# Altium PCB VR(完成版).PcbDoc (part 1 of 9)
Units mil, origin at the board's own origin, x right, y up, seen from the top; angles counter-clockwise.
Board outline 2839.68 x 2020.7 mil, 6 copper layers (TOP, GND02, SIN03, SIN04, PWR05, BOTTOM); 494 components, 404 nets, 7124 pads, 1123 vias.
Unrouted connection lines stored in the file: 10.
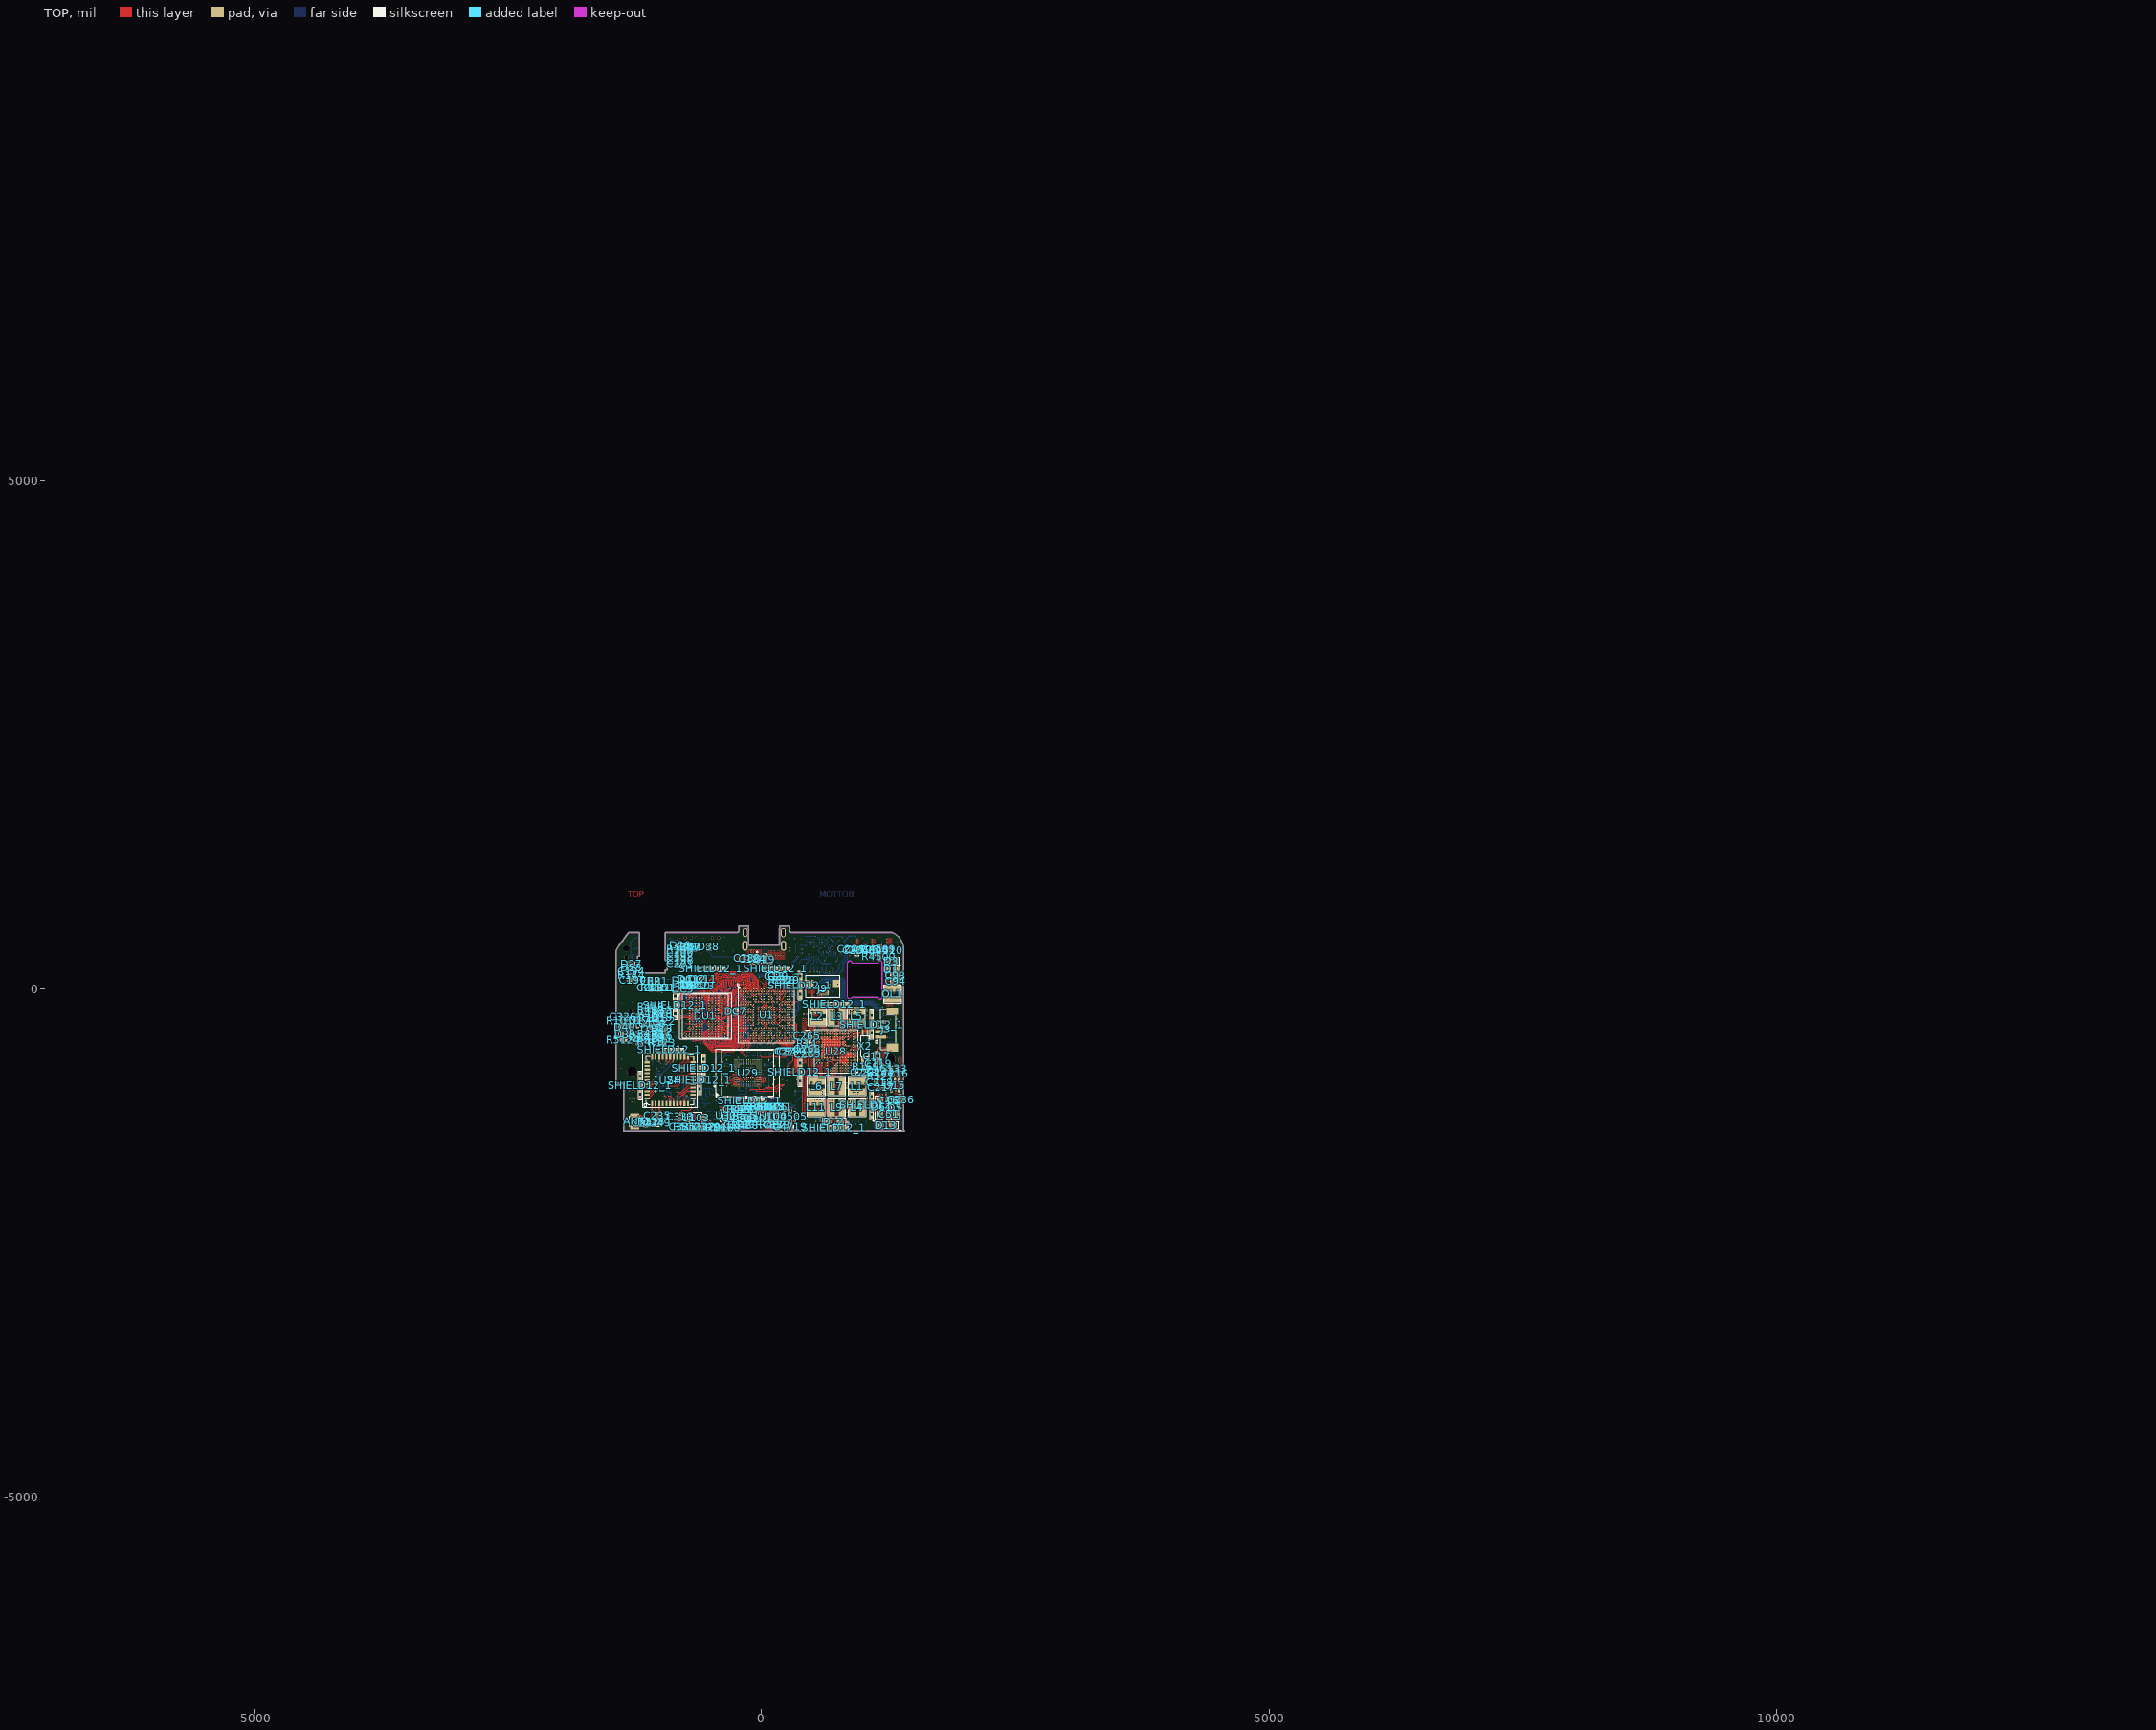
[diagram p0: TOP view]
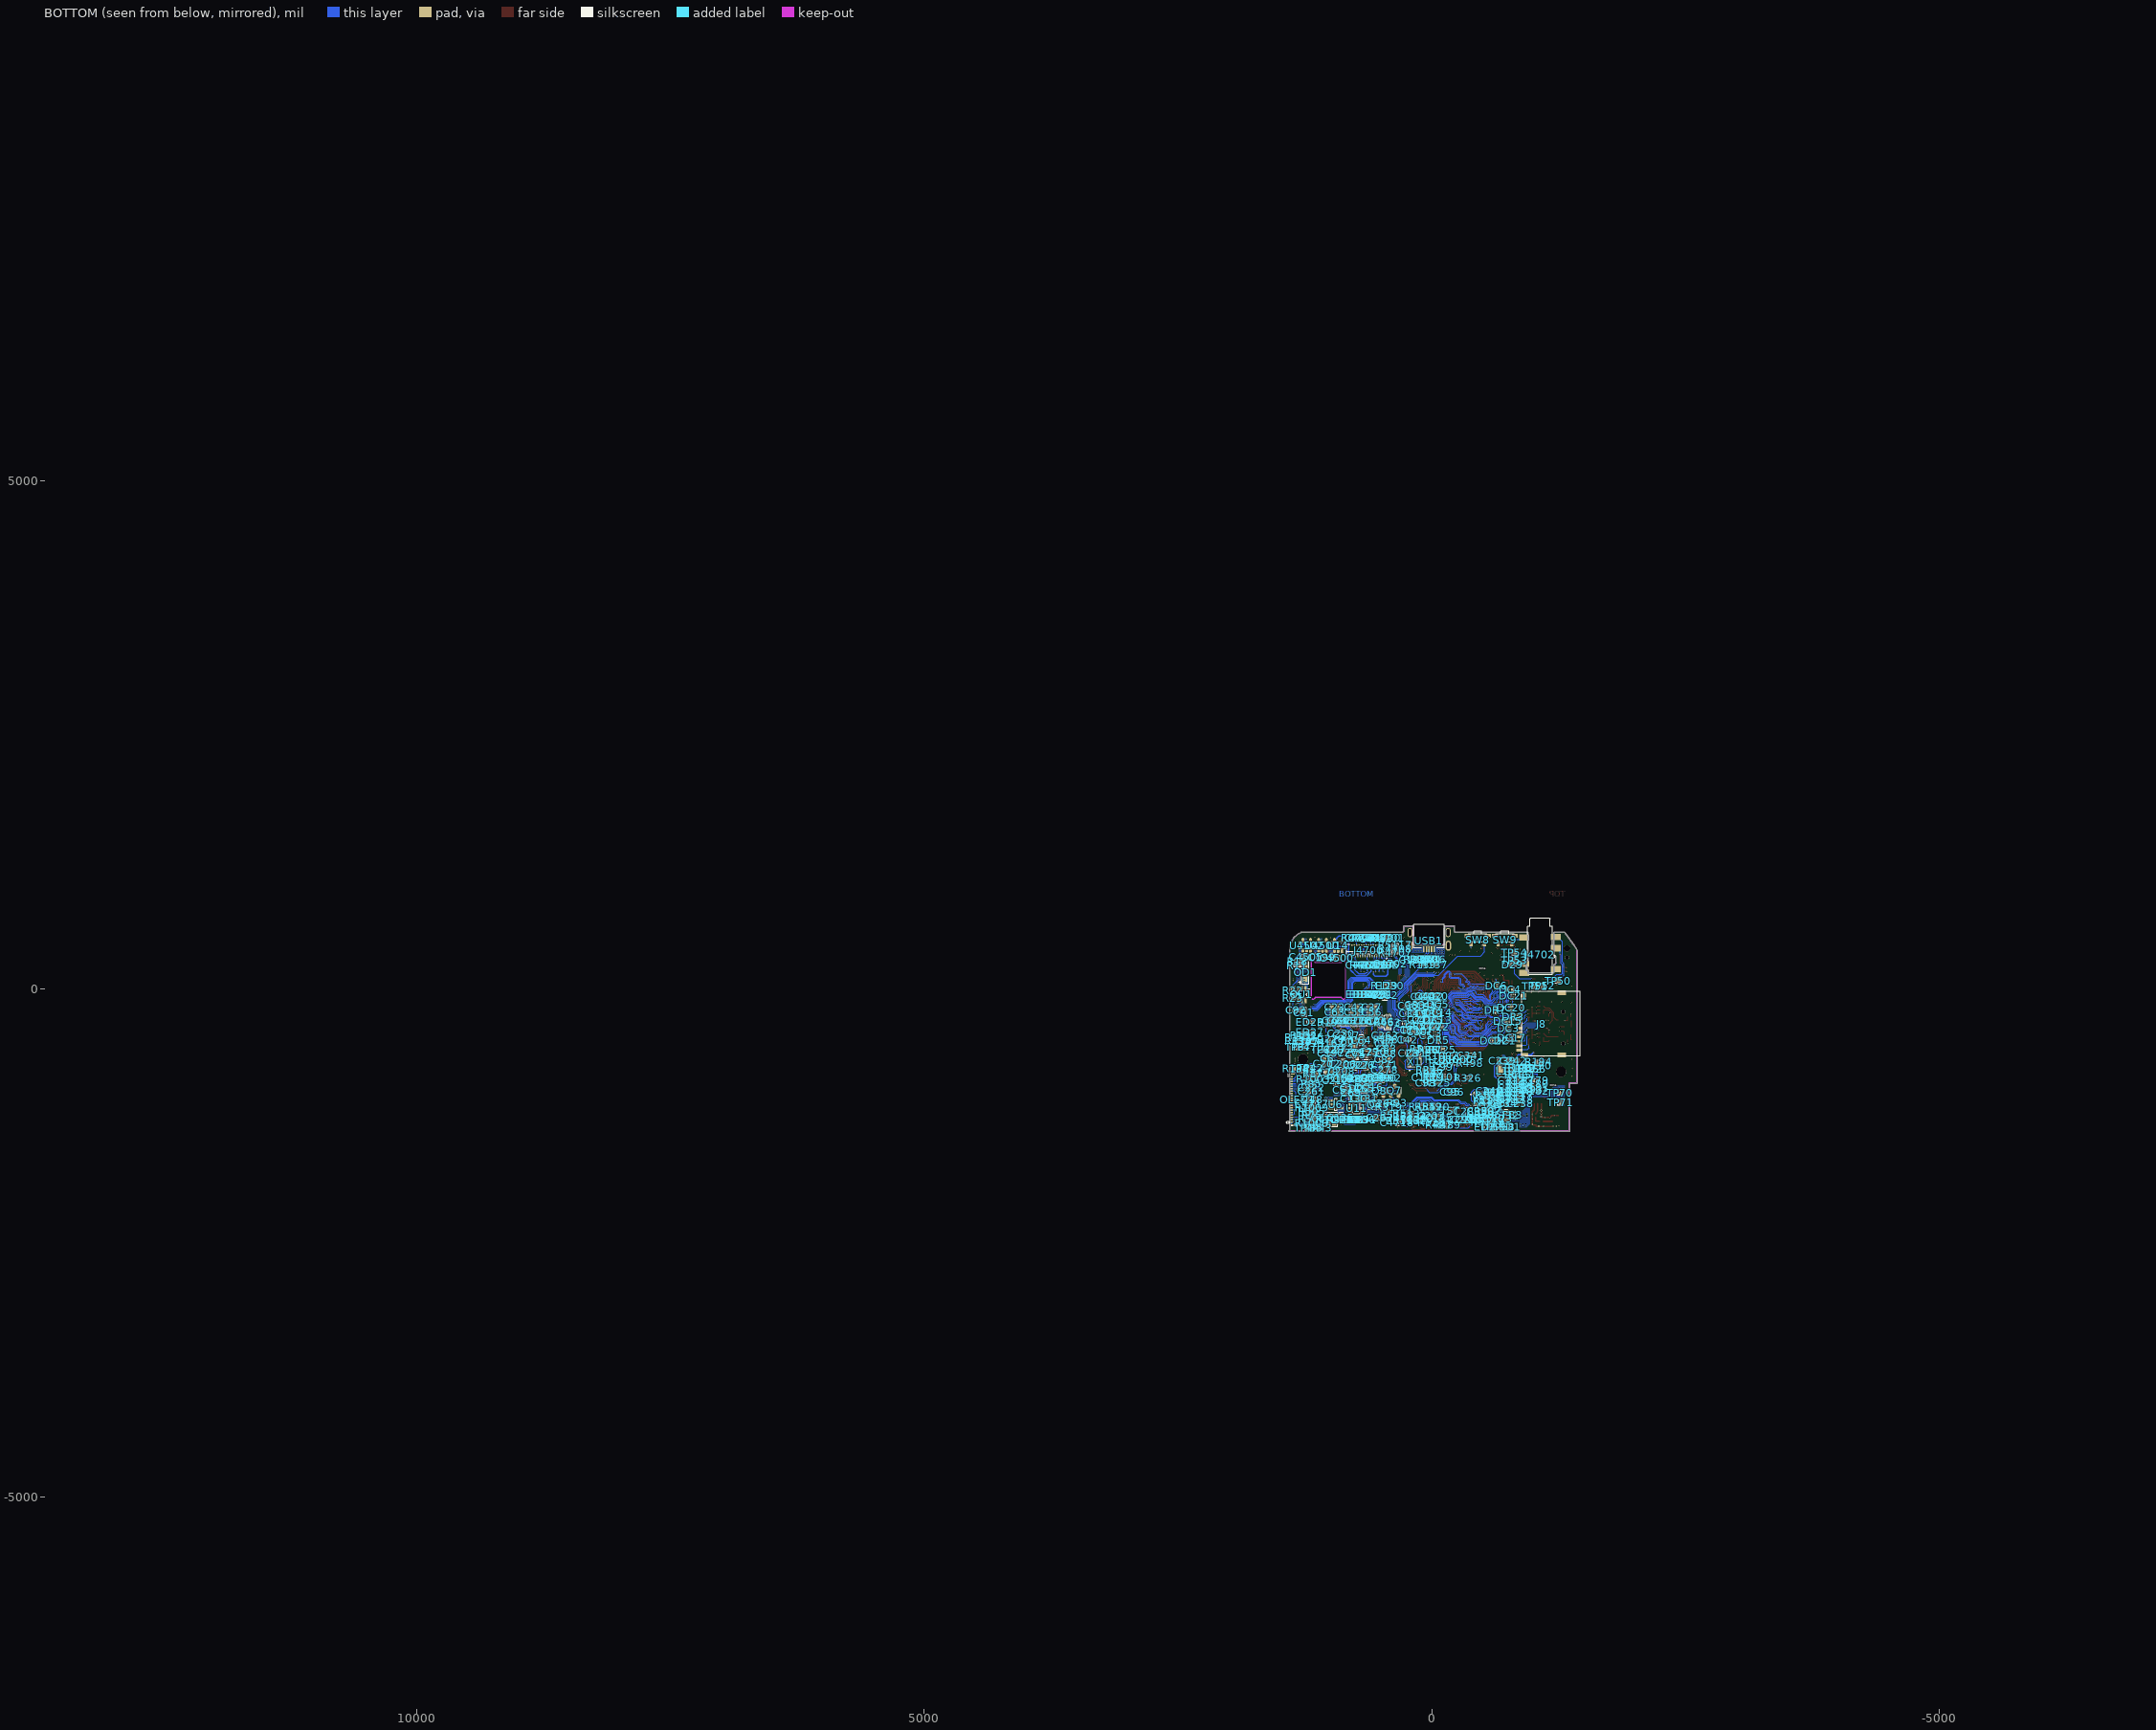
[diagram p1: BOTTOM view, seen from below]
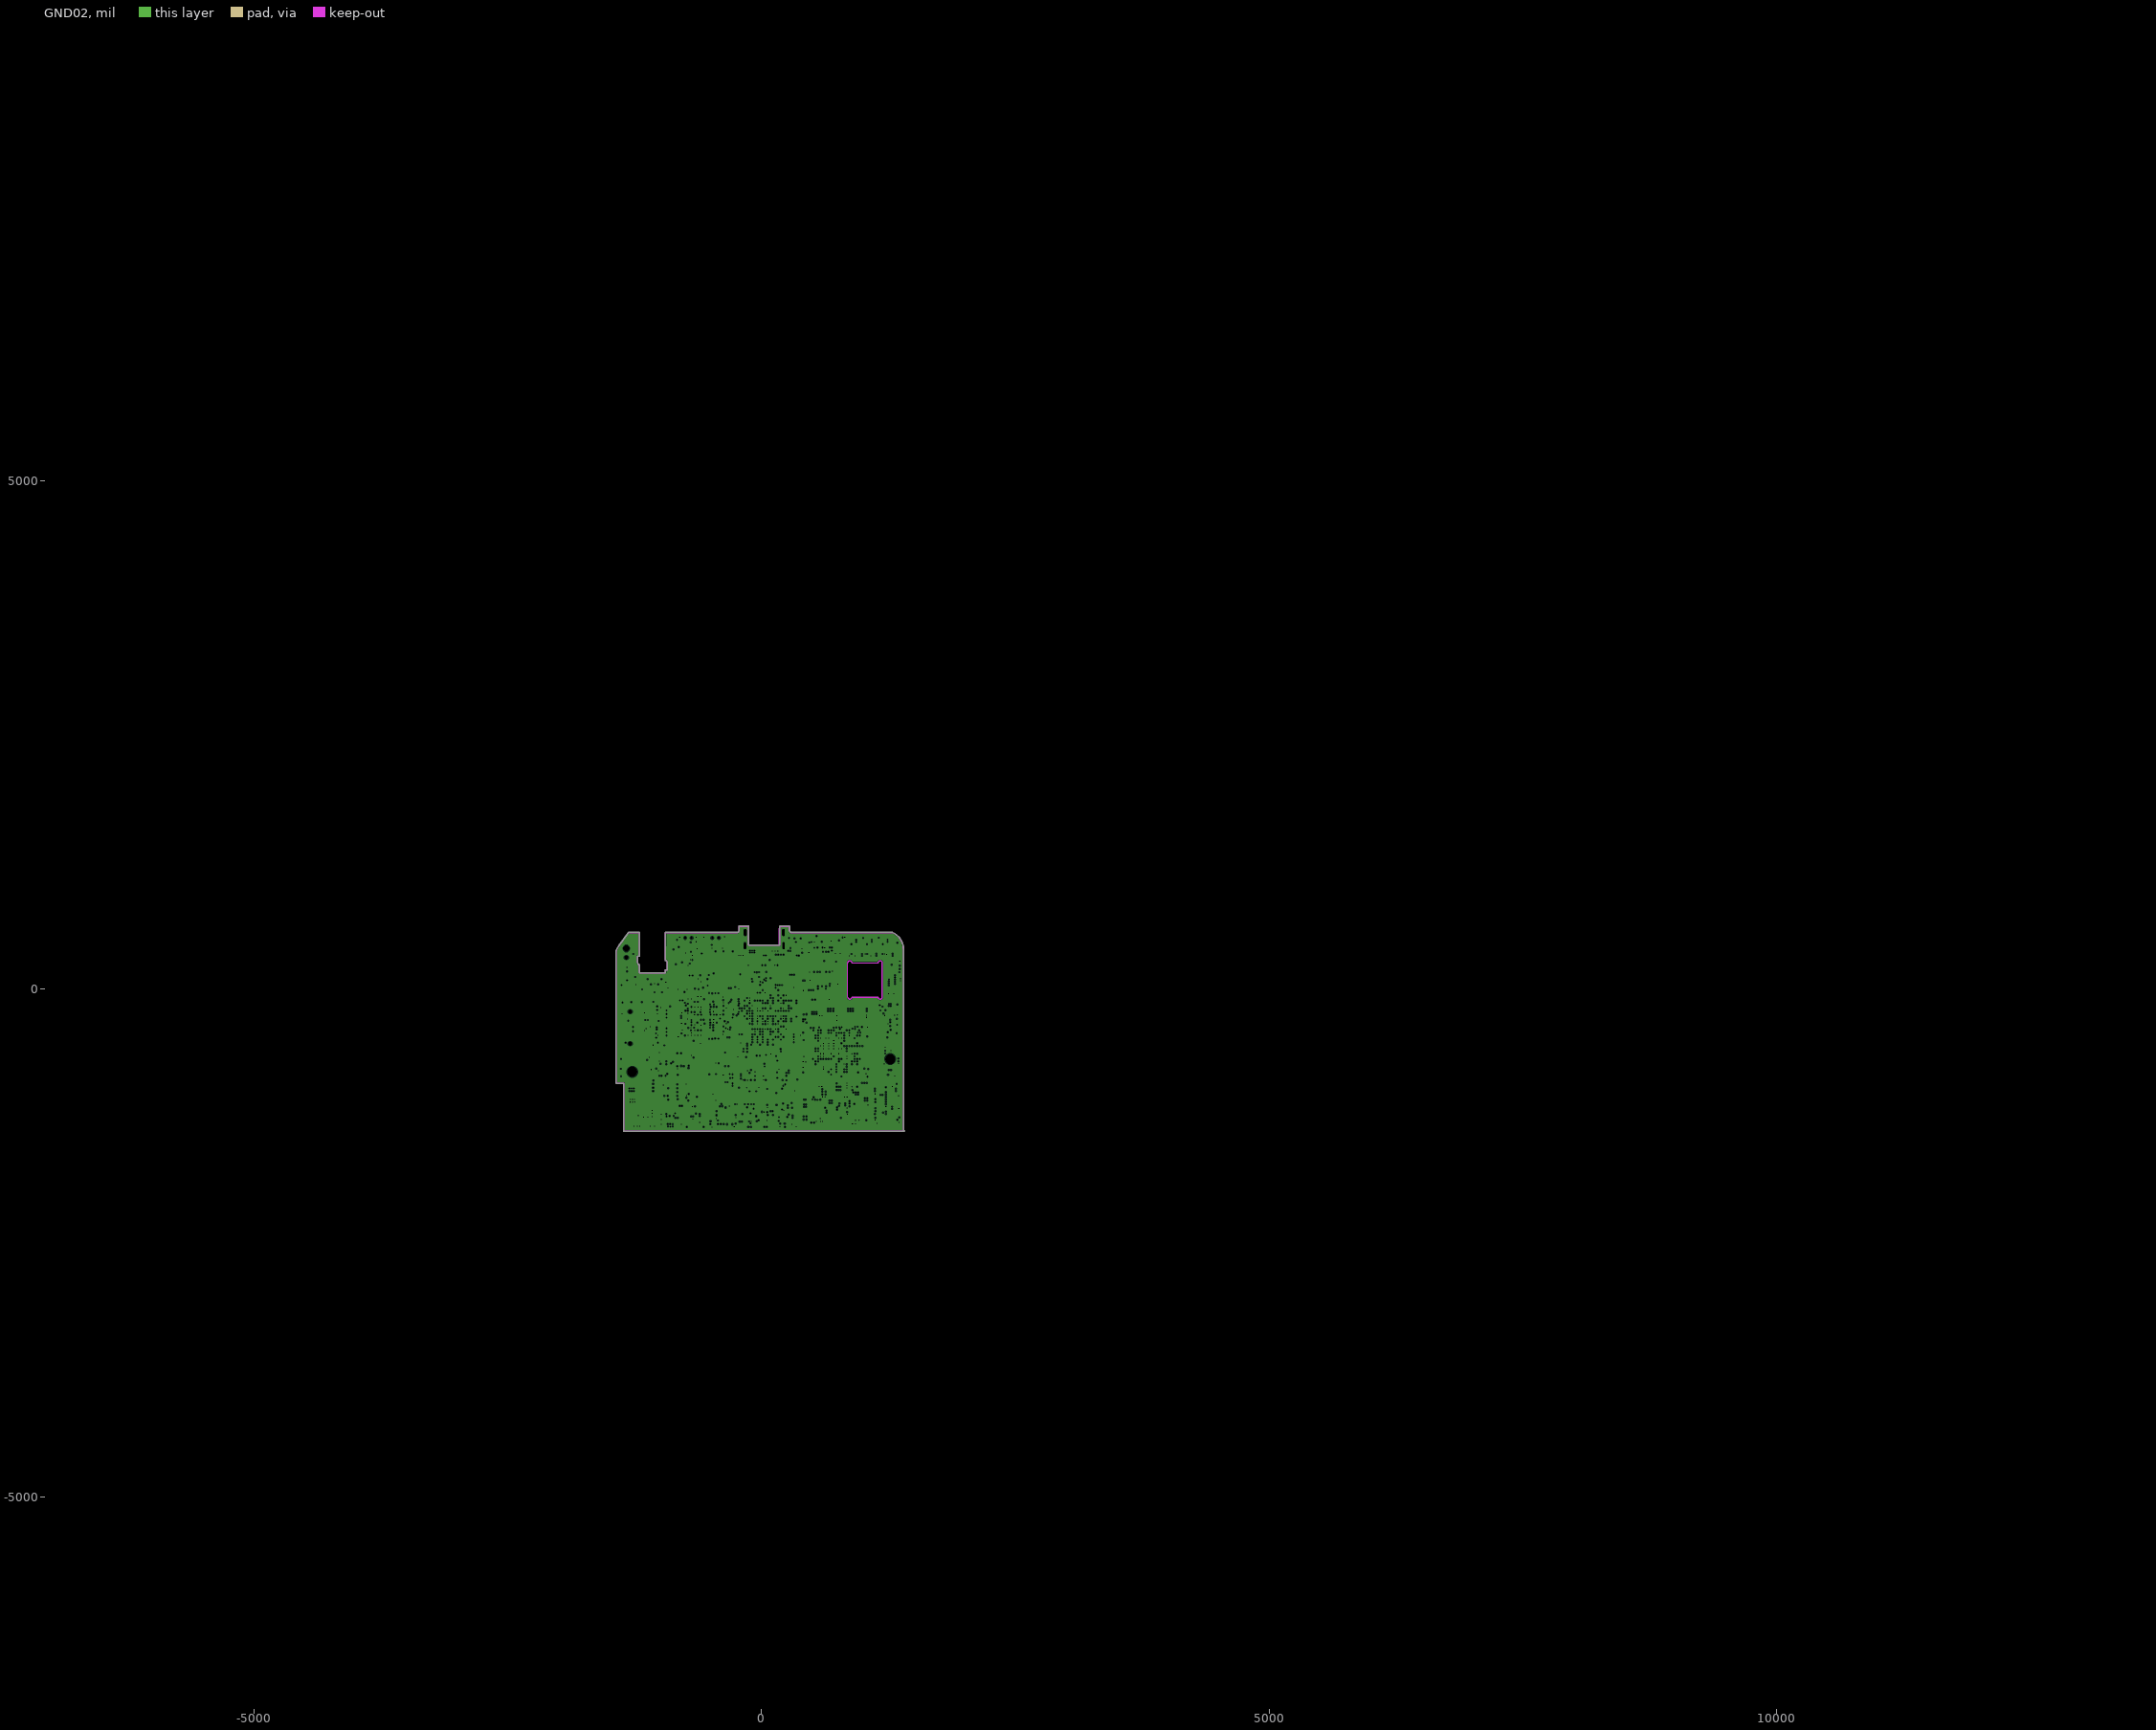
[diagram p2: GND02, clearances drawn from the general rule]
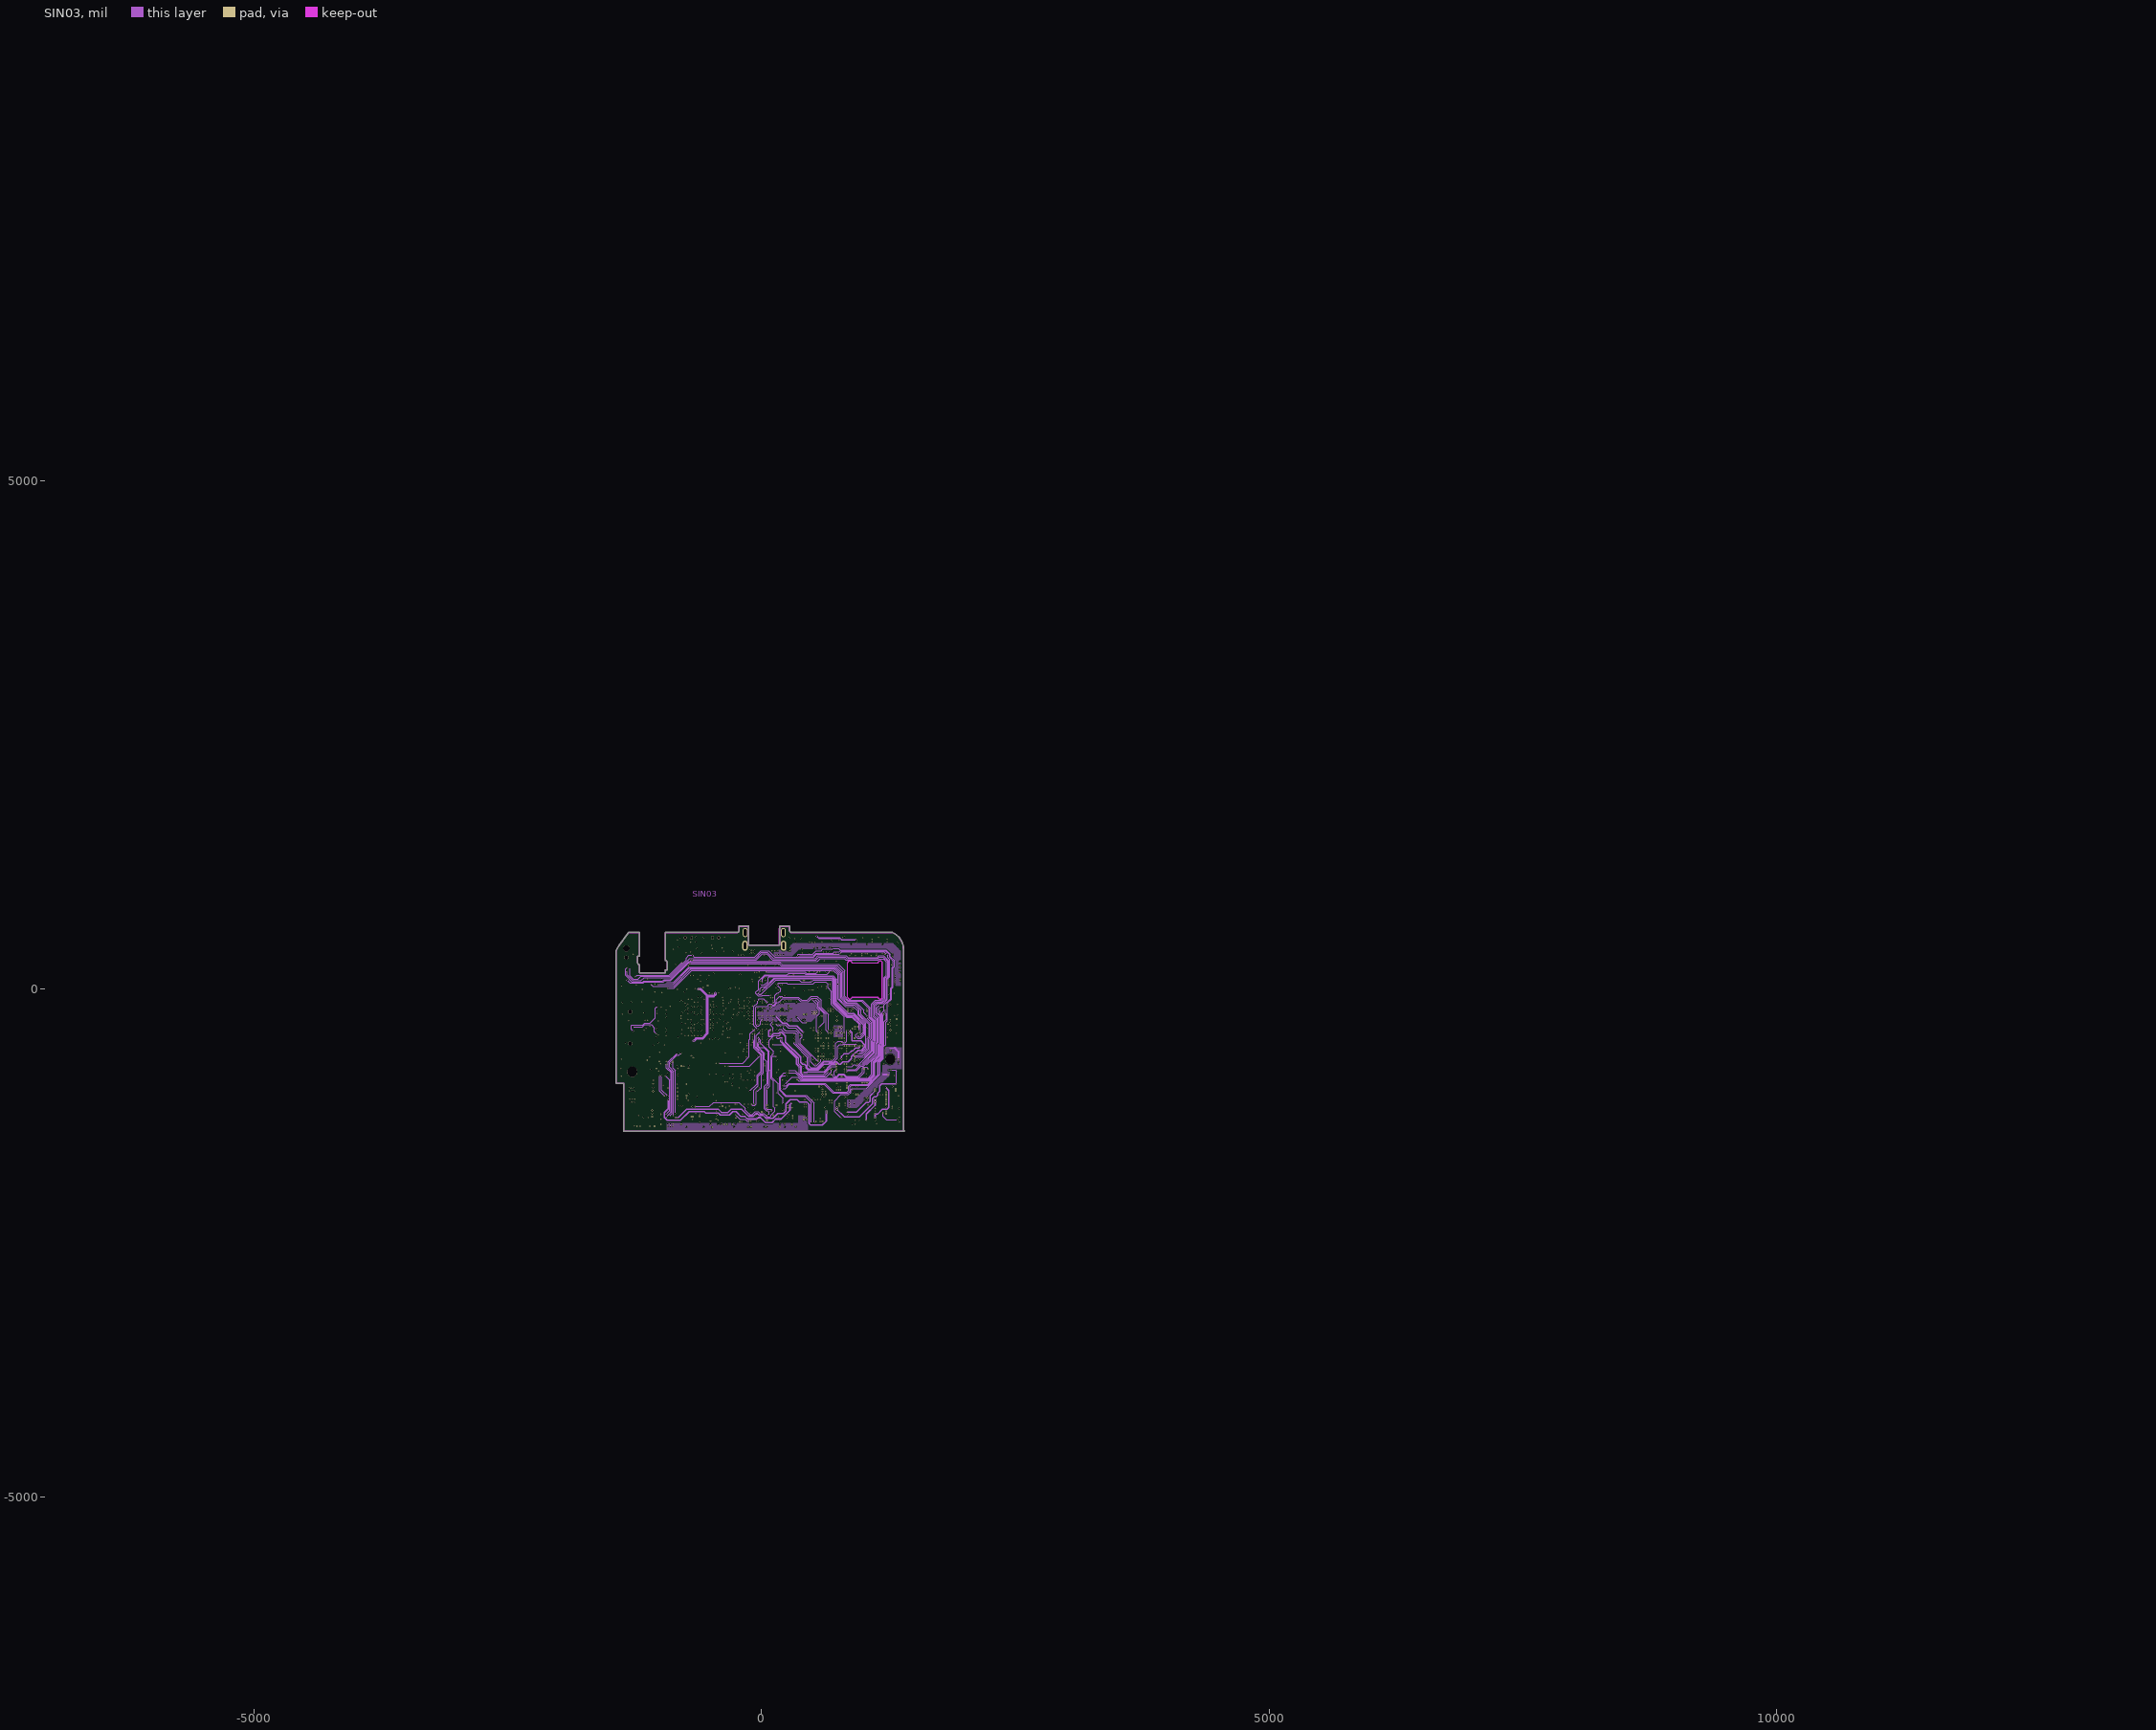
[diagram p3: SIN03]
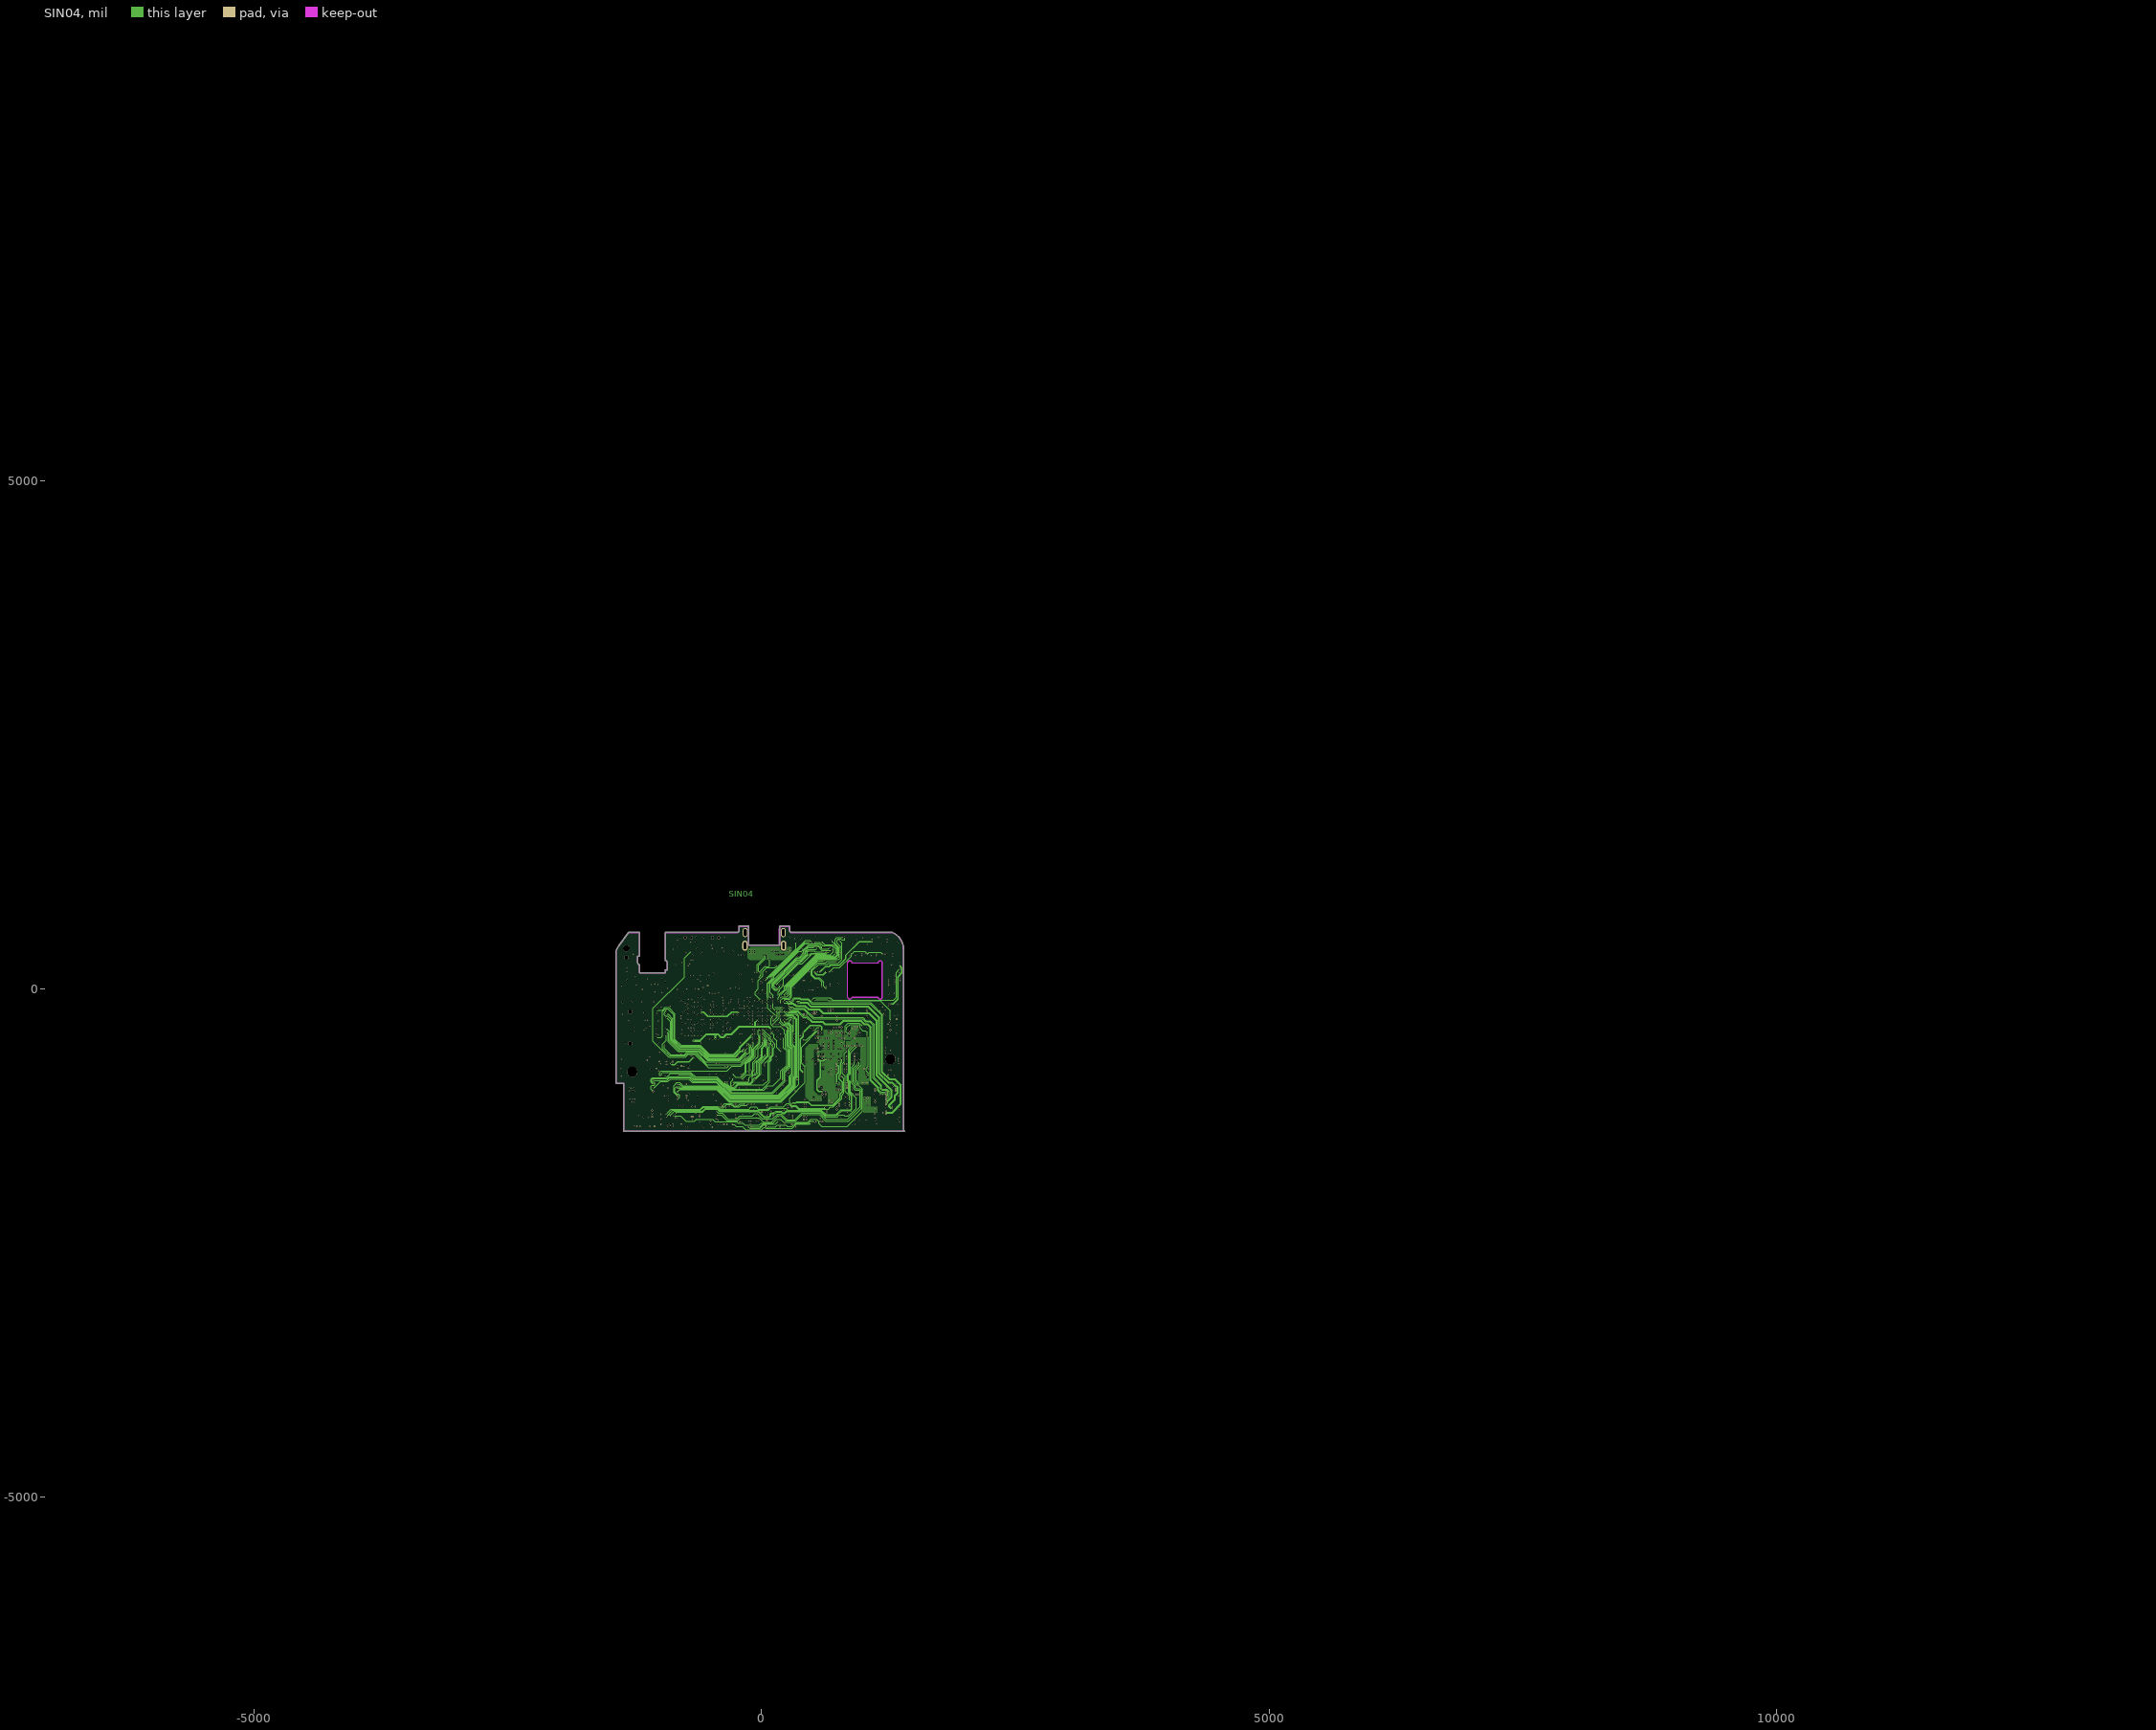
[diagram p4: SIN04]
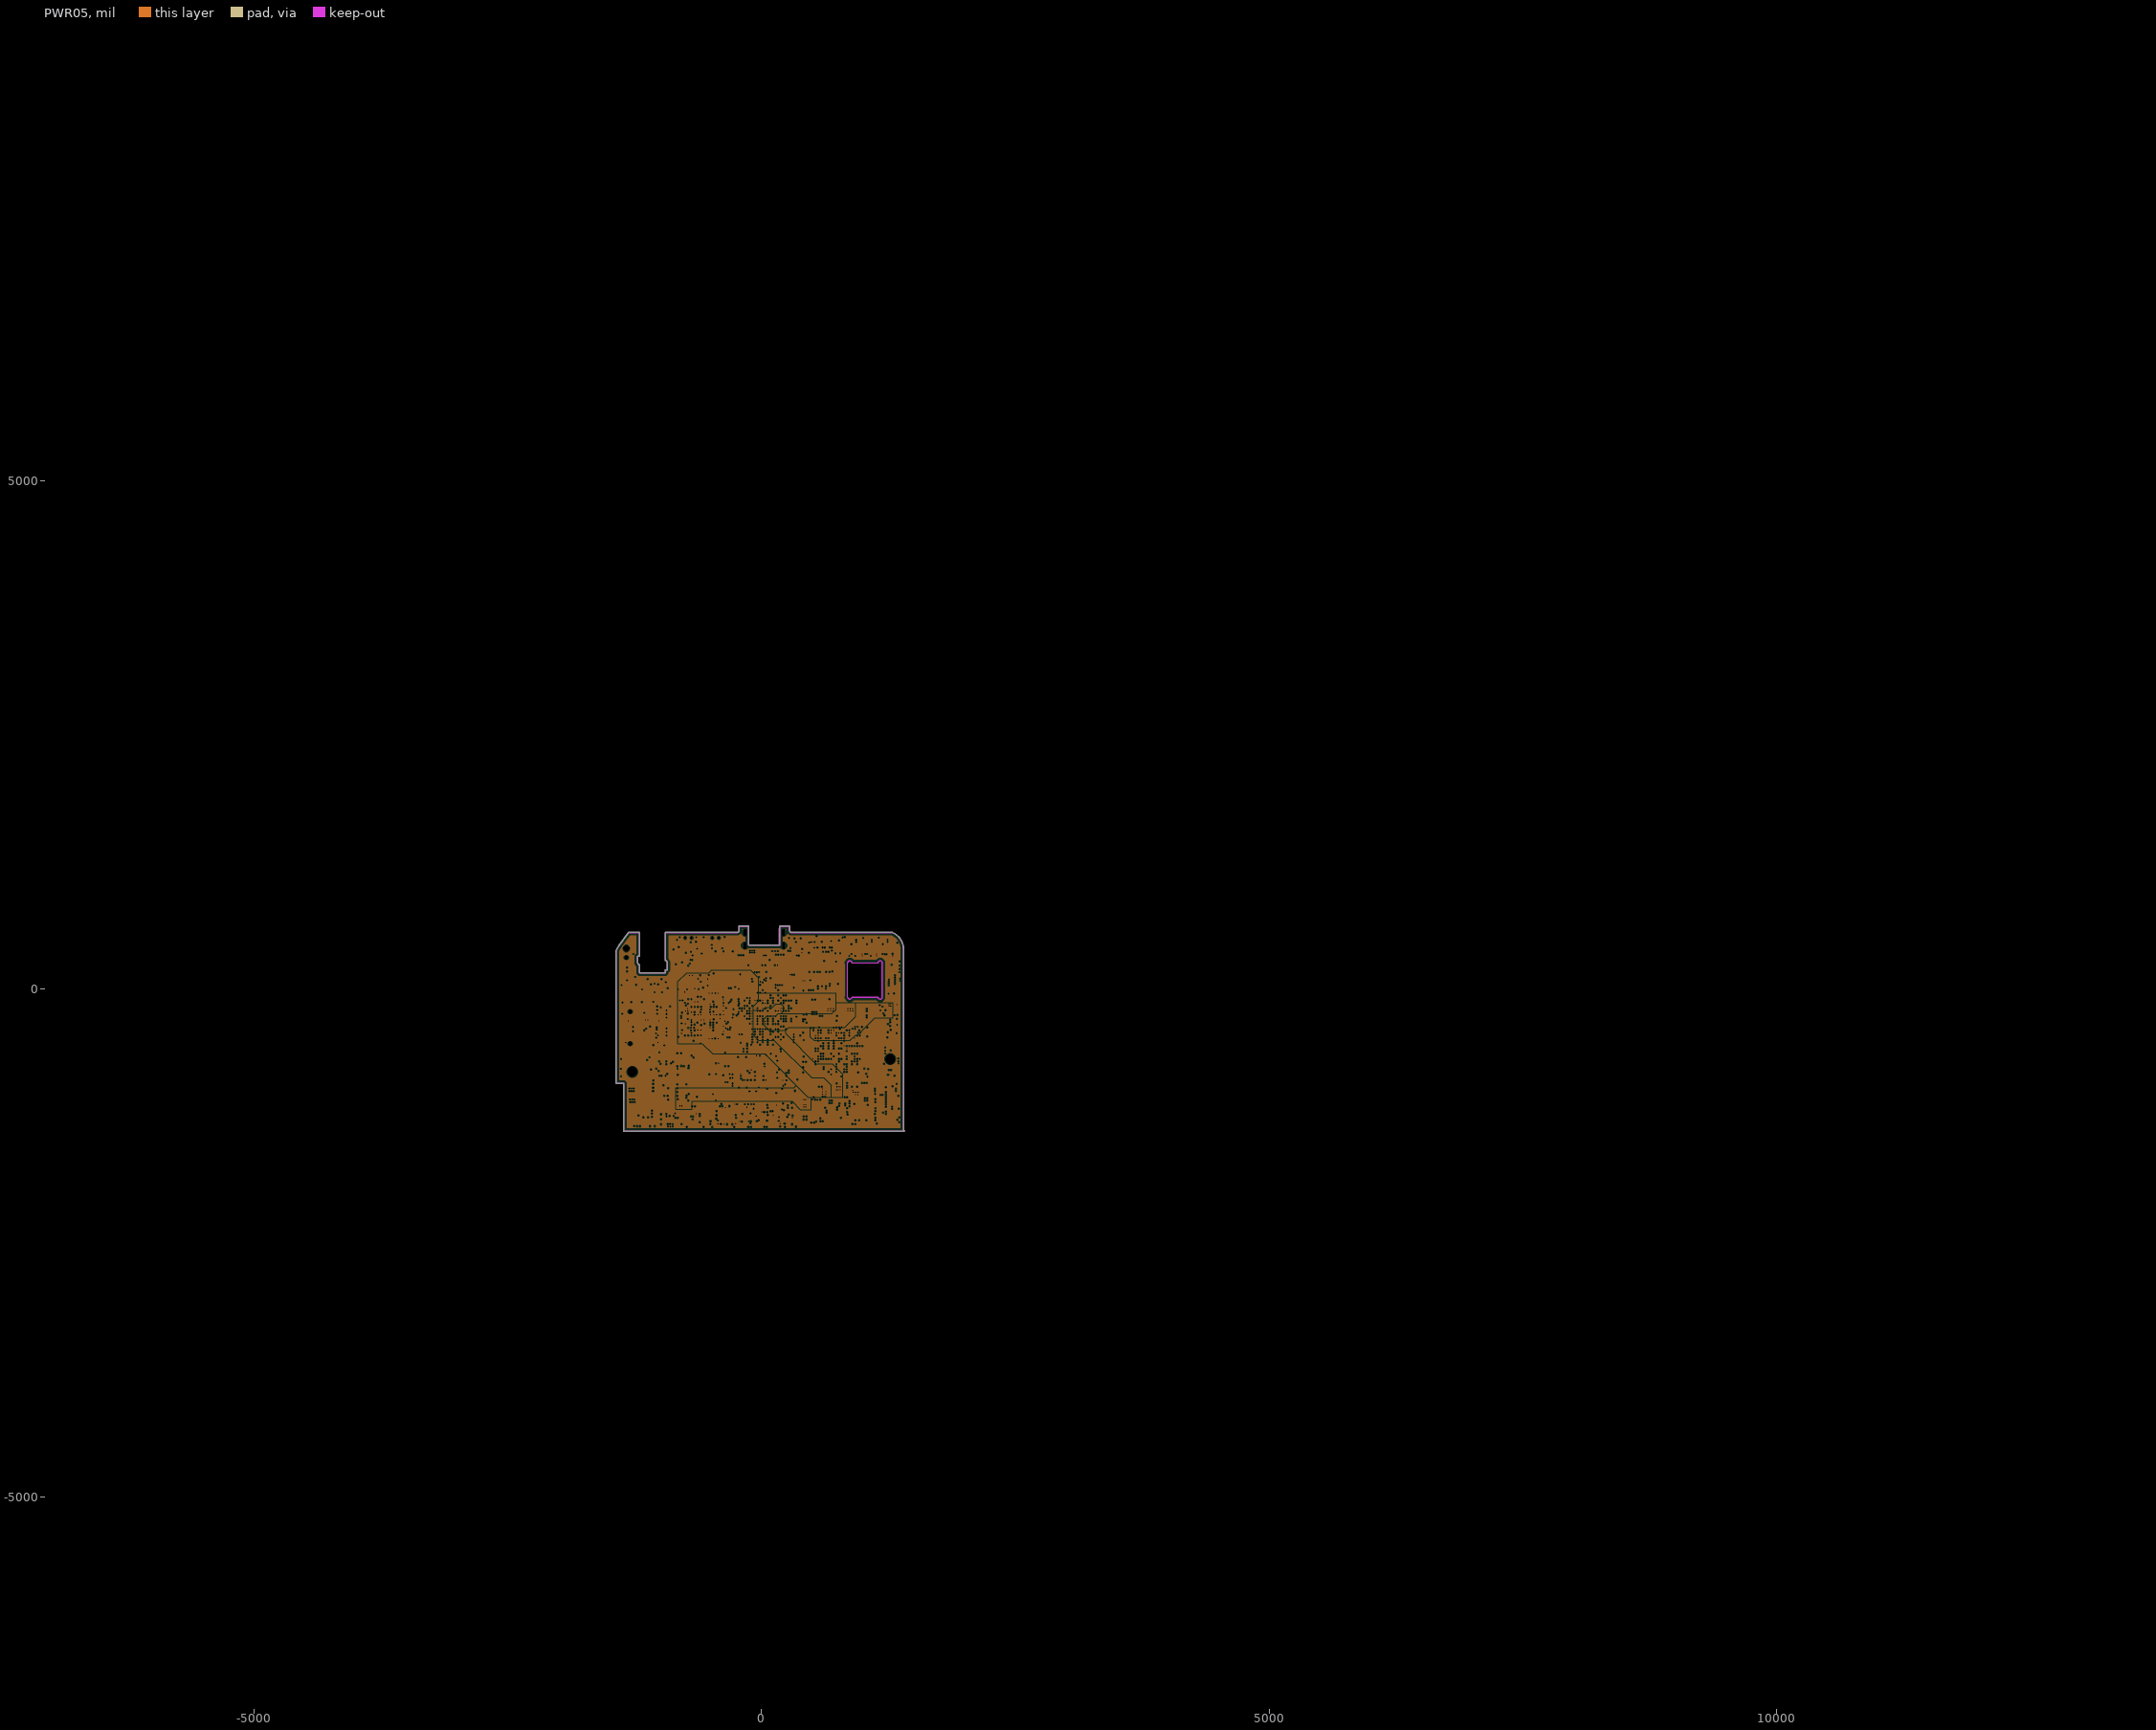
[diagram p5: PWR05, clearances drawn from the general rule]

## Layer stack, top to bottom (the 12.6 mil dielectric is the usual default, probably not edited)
TOP: signal copper 1.4
Dielectric: core 12.6, FR-4, Dk 4.8
GND02: plane copper 1.4, net GND
Dielectric: prepreg 12.6, FR-4, Dk 4.8
SIN03: signal copper 1.4
Dielectric: core 12.6, FR-4, Dk 4.8
SIN04: signal copper 1.4
Dielectric: prepreg 12.6, FR-4, Dk 4.8
PWR05: plane copper 1.4, net DCDC1
Dielectric: core 12.6, FR-4, Dk 4.8
BOTTOM: signal copper 1.4

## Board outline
-1428.06,-929.41 -1355.77,-929.41 -1355.77,-1399.33 ccw(c-1353.25,-1399.33) -1353.25,-1401.85 1406.59,-1401.85 ccw(c1406.59,-1399.33) 1409.11,-1399.33 ccw(c1406.59,-1399.33) 1406.59,-1396.82 1396.58,-1396.82 ccw(c1359.35,-1261.54) 1399.44,-1396 ccw(c1398.72,-1393.59) 1401.23,-1393.59 1401.23,389.68 ccw(c1398.72,389.68) 1401.23,389.7 cw(c1221.55,389.68) 1401.23,389.68 1401.23,389.7 ccw(c1221.55,389.68) 1290.15,555.75 ccw(c1289.19,553.42) 1289.19,555.94 296.35,555.94 cw(c296.35,573.11) 279.18,573.11 279.18,616.33 ccw(c276.67,616.33) 276.67,618.85 184.15,618.85 ccw(c184.15,616.33) 181.63,616.33 181.63,431.85 -124.36,431.85 -124.36,616.33 ccw(c-126.87,616.33) -126.87,618.85 -219.39,618.85 ccw(c-219.39,616.33) -221.91,616.33 -221.91,573.03 ccw(c-219.39,573.03) -221.91,573.01 ccw(c-239.08,573.03) -221.91,573.03 -221.91,573.01 cw(c-239.08,573.03) -239.06,555.86 ccw(c-239.08,553.34) -239.08,555.86 -943.8,555.86 ccw(c-943.8,553.34) -946.32,553.34 -946.32,282.99 ccw(c-943.8,282.99) -944.4,280.55 ccw(c-949.71,260.12) -944.43,280.55 -944.4,280.55 cw(c-949.71,260.12) -928.6,260.12 -928.6,187.83 -943.8,187.83 ccw(c-943.8,185.31) -946.32,185.31 -946.32,158.3 -1199.16,158.3 -1199.16,236.82 ccw(c-1201.68,236.82) -1201.28,239.31 ccw(c-1197.74,260.12) -1201.26,239.3 -1201.28,239.31 cw(c-1197.74,260.12) -1218.85,260.12 -1218.85,320.59 -1201.68,320.59 ccw(c-1201.68,323.11) -1199.16,323.11 -1199.16,553.34 ccw(c-1201.68,553.34) -1201.68,555.86 -1307.34,555.86 ccw(c-1307.34,553.34) -1309.28,554.94 ccw(c-1215.93,478.54) -1313.81,549.04 -1402.19,426.35 ccw(c-1400.16,424.86) -1402.2,426.33 ccw(c-1144.59,240.78) -1430.32,379.16 ccw(c-1428.06,378.07) -1430.57,378.07 -1430.57,-926.89 ccw(c-1428.06,-926.89)
cut-out: 851.47,-81.49 851.47,257.09 cw(c871.16,257.09) 890.84,257.09 1150.68,257.09 cw(c1170.37,257.09) 1190.06,257.09 1190.05,257.09 1190.05,-81.49 1190.06,-81.49 cw(c1170.37,-81.49) 1150.68,-81.49 890.84,-81.49 cw(c871.16,-81.49)

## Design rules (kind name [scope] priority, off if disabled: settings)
Clearance VIA-POLY [(INPolygon) vs ISVIA] p1: gap=5
Clearance poly [inpoly] p2: gap=10
Clearance all [All] p3: gap=3.9
DiffPairsRouting DiffPair_100DiffPairsRouting [InDifferentialPairClass('100om')] p1: maxlimit=6 minlimit=5 mostfreqgap=6 toplayer_maxgap=5 toplayer_prefgap=5 midlayer1_mingap=6 midlayer2_mingap=6 bottomlayer_maxgap=5 bottomlayer_prefgap=5 maxuncoupledlength=500
DiffPairsRouting DiffPair_90DiffPairsRouting [InDifferentialPairClass('90om')] p2: maxlimit=6 minlimit=5 mostfreqgap=6 toplayer_maxgap=5 toplayer_prefgap=5 midlayer1_mingap=6 midlayer2_mingap=6 bottomlayer_maxgap=5 bottomlayer_prefgap=5 maxuncoupledlength=500
MatchedLengths DiffPair_100MatchedLengths [InDifferentialPairClass('100om')] p1: tolerance=1000 checknetsindiffpair=TRUE checkdiffpairvsdiffpair=TRUE checkothers=TRUE
MatchedLengths DiffPair_90MatchedLengths [InDifferentialPairClass('90om')] p2: tolerance=1000 checknetsindiffpair=TRUE checkdiffpairvsdiffpair=TRUE checkothers=TRUE
PlaneClearance [All] p1: clearance=7
PlaneConnect [All] p1: planeconnectstyle=Direct reliefexpansion=20 reliefentries=4 reliefconductorwidth=10 reliefairgap=10
PolygonConnect [All] p1: connectstyle=Direct reliefconductorwidth=10 reliefentries=4 polygonreliefangle="90 Angle"
RoutingVias [All] p1: holewidth=8 width=16 viastyle="Through Hole" minholewidth=8 minwidth=16 maxholewidth=8 maxwidth=16
SilkscreenOverComponentPads [IsPad] p1: minsilkscreentomaskgap=10
SolderMaskExpansion [All] p1: expansion=2.5
Width DiffPair_100Width [InDifferentialPairClass('100om')] p1: maxlimit=4.5 minlimit=4 preferedwidth=4.5 toplayer_maxwidth=4 toplayer_prefwidth=4 midlayer1_minwidth=4.5 midlayer2_minwidth=4.5 bottomlayer_maxwidth=4 bottomlayer_prefwidth=4 minimp=50.000000 maximp=50.000000 favimp=50.000000
Width DiffPair_90Width [InDifferentialPairClass('90om')] p2: maxlimit=5.5 minlimit=5 preferedwidth=5.5 toplayer_maxwidth=5 toplayer_prefwidth=5 midlayer1_minwidth=5.5 midlayer2_minwidth=5.5 bottomlayer_maxwidth=5 bottomlayer_prefwidth=5 minimp=50.000000 maximp=50.000000 favimp=50.000000
Width PWR [InNetClass('PWR')] p3: maxlimit=15 minlimit=6 preferedwidth=12
Width ALL-W [All] p4: maxlimit=5 minlimit=4 preferedwidth=5 toplayer_minwidth=5 midlayer1_maxwidth=4 midlayer1_prefwidth=4 midlayer2_maxwidth=4 midlayer2_prefwidth=4 bottomlayer_minwidth=5 minimp=50.000000 maximp=50.000000 favimp=50.000000
24 further rules are at their usual default settings.

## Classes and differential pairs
differential pair class 100om: D_MIPI-CSI2-CL D_MIPI-CSI2-D D_MIPI-DSI-C D_MIPI-DSI-D MIPI-DSI-D0 MIPI-DSI-D1 MIPI-DSI-D3
differential pair class 90om: D_USB-D0 D_USB-D1

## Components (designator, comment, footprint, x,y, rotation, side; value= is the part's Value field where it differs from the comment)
ANT1 "ANT" CON2-WIFI-PT4 -1217.27,-1304.86 r270 top locked
C3 "104" C0402 -38,-436.14 r270 bottom locked
C4 "104" C0402 140,-77.86 r90 bottom locked
C5 "104" C0402 51.86,-458 r0 bottom locked
C6 "10uF" C0603 1030.06,-685 r180 bottom locked
C7 "104" C0402 51.86,-418 r180 bottom locked
C8 "1uF" C0402 222,-614.78 r270 top locked
C11 "104" C0402 208.14,-410 r180 bottom locked
C12 "104" C0402 -22,-75.86 r270 bottom locked
C13 "104" C0402 132,125 r90 top locked
C14 "104" C0402 803.87,-977 r180 bottom locked
C15 "104" C0402 118,-181 r90 bottom locked
C16 "10uF" C0603 1258.56,-1101.77 r90 top locked
C17 "1uF" C0402 274,-402.14 r90 bottom locked
C18 "104" C0402 251.86,-345 r180 bottom locked
C19 "1uF" C0402 137.86,-242 r0 bottom locked
C20 "104" C0402 -64,-74.86 r270 bottom locked
C21 "1uF" C0402 138,-306.14 r90 bottom locked
C22 "104" C0402 -76.14,-373 r0 bottom locked
C23 "10uF" C0603 952.52,-181.48 r180 bottom locked
C24 "1uF" C0402 2.86,-371 r0 bottom locked
C25 "1uF" C0402 -12,-309 r270 bottom locked
C26 "104" C0402 38,-315 r270 bottom locked
C27 "104" C0402 80.14,-369 r180 bottom locked
C28 "18pF" C0402 226.67,-634.86 r180 bottom locked
C29 "104" C0402 173,124.14 r270 top locked
C30 "104" C0402 145,-424.14 r270 bottom locked
C31 "18pF" C0402 146.05,-634.86 r0 bottom locked
C33 "1uF" C0402 163,-158.86 r270 bottom locked
C34 "1uF" C0402 218.14,-244 r180 bottom locked
C35 "104" C0402 153.14,-368 r180 bottom locked
C36 "104" C0402 230.14,-168 r180 bottom locked
C37 "10uF" C0603 588.52,-181.48 r180 bottom locked
C38 "1uF" C0402 64.14,-243 r180 bottom locked
C39 "1uF" C0402 -6.14,-243 r0 bottom locked
C41 "104" C0402 89,-307.14 r90 bottom locked
C42 "102" C0402 238,-503 r180 bottom locked
C43 "10uF" C0603 760,-181.48 r180 bottom locked
C44 "1uF" C0402 63,-74.86 r270 bottom locked
C45 "1uF" C0402 42.14,-163 r180 bottom locked
C46 "104" C0402 18,-75.86 r270 bottom locked
C47 "104" C0402 -15,-177.86 r270 bottom locked
C48 "10uF" C0603 1168.67,-1091.86 r0 bottom locked
C50 "10uF" C0603 859.47,-518.24 r0 bottom locked
C51 "10uF" C0603 1258.16,-1235.03 r270 top locked
C53 "10uF" C0603 871.41,-997.3 r270 bottom locked
C56 "10uF" C0603 588.73,-231 r0 bottom locked
C57 "10uF" C0603 613.73,-314.97 r90 bottom locked
C59 "10uF" C0603 761,-231 r0 bottom locked
C61 "10uF" C0603 665.44,-314.97 r90 bottom locked
C63 "10uF" C0603 952.73,-231 r0 bottom locked
C64 "10uF" C0603 695.41,-506.3 r270 bottom locked
C65 "10uF" C0603 662.78,-982.56 r270 bottom locked
C66 "10uF" C0603 873.58,-313.97 r90 bottom locked
C67 "104" C0402 457.29,-540.48 r180 bottom locked
C68 "10uF" C0603 600.41,-874.8 r270 bottom locked
C69 "10uF" C0603 794.79,-1024.86 r180 bottom locked
C70 "10uF" C0603 562.41,-315.18 r270 bottom locked
C71 "10uF" C0603 820.41,-316.18 r270 bottom locked
C72 "10uF" C0603 769.41,-753.92 r270 bottom locked
C74 "4.7uF" C0603 925.7,-314.18 r270 bottom locked
C75 "4.7uF" C0603 744.73,-648.8 r90 bottom locked
C76 "4.7uF" C0603 977.41,-314.18 r270 bottom locked
C77 "4.7uF" C0603 648.41,-751.8 r270 bottom locked
C78 "4.7uF" C0603 1014,-822 r180 bottom locked
C79 "472" C0402 -730.27,412.83 r270 top locked
C81 "4.7uF" C0603 769.27,-315.18 r270 bottom locked
C82 "10uF" C0603 463.14,-692.98 r180 bottom locked
C83 "4.7uF" C0603 441.67,-586.24 r180 bottom locked
C88 "10uF" C0603 443.67,-640.24 r0 bottom locked
C89 "4.7uF" C0603 494.73,-876.92 r90 bottom locked
C90 "4.7uF" C0603 546.41,-874.8 r90 bottom locked
C91 "10uF" C0603 1261,-232 r90 bottom locked
C92 "1uF" C0402 1333.42,-210.86 r180 bottom locked
C93 "10uF" C0603 1323.79,128.14 r180 top locked
C94 "10uF" C0603 1323.79,76.14 r180 top locked
C95 "1uF" C0402 -181.64,-1016.55 r90 bottom locked
C96 "104" C0402 -220.6,-1016.55 r90 bottom locked
C98 "1uF" C0402 60.14,-925 r180 bottom locked
C99 "104" C0402 -109.69,-773 r0 bottom locked
C100 "1uF" C0402 61.14,-876 r180 bottom locked
C101 "104" C0402 -144.86,-868 r180 bottom locked
C117 "10uF" C0603 1143.73,-663.39 r270 top locked
C119 "102" C0402 1157.59,-737.86 r180 top locked
C130 "10uF" C0603 764.47,-1080.86 r180 bottom locked
C131 "102" C0402 658.72,-1077.86 r0 bottom locked
C132 "10uF/50V" C0805 1181.38,-812.61 r0 top locked
C133 "104/50V" C0402 1305.73,-782.86 r180 top locked
C134 "1uF" C0402 848.41,-1287.55 r270 bottom locked
C135 "10uF" C0603 896.41,-1269.92 r90 bottom locked
C136 "1uF" C0402 685.21,-1287.55 r90 bottom locked
C176 "10uF" C0603 -1066.33,-341.86 r0 top locked
C179 "104" C0402 154.73,-1340.55 r90 top locked
C180 "104" C0402 116,-1283 r90 bottom locked
C182 "1uF" C0402 184.73,286.56 r90 bottom locked
C183 "104" C0402 -134.27,302.45 r90 top locked
C184 "10uF" C0603 -85.27,294.08 r90 top locked
C185 "104" C0402 -74.58,-1270.86 r90 bottom locked
C186 "104" C0402 -239.27,-1184.17 r270 top locked
C187 "4.7uF" C0603 834,-889.2 r90 bottom locked
C188 "104" C0402 759.41,-884.55 r90 bottom locked
C189 "105" C0402 -192.27,-1342.55 r90 top locked
C190 "10uF" C0603 -1262.21,85.14 r180 top locked
C191 "104" C0402 -228.27,-1342.55 r90 top locked
C194 "104" C0402 -1276.58,172.48 r0 top locked
C196 "33pF" C0402 -795.96,279.74 r0 top locked
C197 "2.2uF" C0402 992.1,-633.86 r0 bottom locked
C198 "104" C0402 -795.96,317.34 r180 top locked
C199 "4.7uF" C0603 1081.67,307.14 r180 bottom locked
C200 "NC/33pF" C0402 -795.96,354.94 r180 top locked
C201 "NC/33pF" C0402 -795.96,242.14 r0 top locked
C202 "10uF" C0603 1032,-737 r0 bottom locked
C203 "104" C0402 2.34,-1253.17 r0 bottom locked
C204 "0.1uF" C0402 886.73,391 r270 top locked
C205 "4.7uF" C0603 940.73,378.08 r270 top locked
C206 "10uF" C0603 873.41,-743.8 r270 bottom locked
C208 "104" C0402 887.1,-814.86 r180 bottom locked
C209 "104" C0402 -1088.27,9.83 r90 top locked
C211 "104" C0402 -1014.94,9.83 r90 top locked
C212 "4.7uF" C0603 941.84,-903.31 r90 bottom locked
C216 "4.7uF" C0603 1319.67,-832.86 r180 top locked
C217 "0.1uF" C0402 1182.04,-969.53 r180 top locked
C218 "4.7uF" C0603 1167.67,-920.63 r180 top locked
C222 "0.1uF" C0402 1184.04,-973.63 r180 bottom locked
C226 "104" C0402 692.73,-751 r90 bottom locked
C227 "104" C0402 840.98,-459.49 r90 bottom locked
C228 "104" C0402 991.87,-492.86 r180 bottom locked
C229 "104" C0402 991.44,-596.86 r180 bottom locked
C230 "104" C0402 890.41,-440.55 r90 bottom locked
C232 "18pF" C0402 1052.66,-822.55 r90 top locked
C233 "18pF" C0402 1012.66,-822.55 r90 top locked
C234 "10uF" C0603 -709.21,-1129.86 r180 bottom locked
C235 "33pF" C0402 -1021.27,-1248.72 r90 top locked
C236 "0.1uF" C0402 1379,-1089.14 r270 top locked
C238 "1uF" C0402 -870.96,-1130.86 r180 bottom locked
C239 "4.7uF" C0603 -697.33,-710.79 r180 bottom locked
C240 "27pF" C0402 -567.14,-1006 r180 bottom locked
C241 "27pF" C0402 -580.96,-1161.86 r180 bottom locked
C242 "4.7uF" C0603 -805.21,-710.79 r180 bottom locked
C247 "NC" C0402 -1136.27,-1323 r270 top locked
C249 "NC" C0402 -1021.27,-1320 r270 top locked
C261 "0.1uF" C0402 1183.04,-1010.63 r180 bottom locked
C263 "10uF" C0603 460.35,-459.24 r0 bottom locked
C264 "1uF" C0402 476.41,-1129.55 r270 bottom locked
C265 "10uF" C0805 454,-462.86 r90 top locked
C266 "10uF" C0805 502.41,-323.64 r270 bottom locked
C267 "10uF" C0603 511.79,-1268.98 r180 bottom locked
C268 "10uF" C0603 459.67,-590.86 r0 top locked
C269 "10uF" C0603 459.67,-642.86 r0 top locked
C270 "10uF" C0603 575.41,-618.24 r180 bottom locked
C271 "4.7uF" C0603 463.14,-745.31 r180 bottom locked
C272 "10uF" C0603 760,-530.94 r90 bottom locked
C273 "10uF" C0603 900.73,-594.86 r0 bottom locked
C275 "4.7uF" C0603 653.41,-628.18 r90 bottom locked
C276 "4.7uF" C0603 717.56,-315.18 r270 bottom locked
C277 "102" C0402 268,-615.14 r270 top locked
C278 "4.7uF" C0603 462.35,-797.24 r180 bottom locked
C279 "4.7uF" C0603 794.41,-631.18 r90 bottom locked
C280 "102" C0402 314,-616.14 r90 top locked
C281 "0.1uF" C0402 510.93,-53.55 r270 bottom locked
C282 "4.7uF" C0603 463.73,-65.92 r270 bottom locked
C289 "10nF" C0402 -353.14,-1207.49 r270 bottom locked
C290 "1uF" C0402 -368.89,-1290.23 r270 bottom locked
C291 "0.1uF" C0402 -291.27,-1288.17 r270 bottom locked
C292 "0.1uF" C0402 -330.27,-1290.17 r90 bottom locked
C312 "NC/33P" C0402 -783.58,-1089.86 r180 bottom locked
C313 "NC/33P" C0402 -783.58,-1052.11 r180 bottom locked
C314 "NC/33P" C0402 -783.58,-1014.36 r180 bottom locked
C315 "NC/33P" C0402 -783.58,-976.61 r180 bottom locked
C316 "NC/33P" C0402 -783.58,-938.86 r180 bottom locked
C317 "NC/33P" C0402 -784.58,-903.86 r180 bottom locked
C326 "1uF" C0402 -1354.96,-277.86 r0 top locked
C327 "1uF" C0402 -484.51,-1279.08 r180 bottom locked
C328 "0.1uF" C0402 -484.89,-1241.08 r180 bottom locked
C329 "100pF-04" C0402 -528.58,-1360.86 r0 top locked
C330 "0.1uF" C0402 -484.89,-1202.08 r180 bottom locked
C331 "100pF-04" C0402 -770.96,-1360.86 r180 top locked
C332 "10uF" C0805 -730.2,-1248.08 r270 bottom locked
C333 "0.1uF" C0402 -796.2,-1256.24 r90 top locked
C341 "4.7uF" C0603 -385.94,-658 r180 bottom locked
C4500 "4.7uF" C0603 934.67,304.14 r180 bottom locked
C4504 "4.7uF" C0603 1096.73,378.08 r270 top locked
C4505 "4.7uF" C0603 1236.67,311.58 r180 bottom locked
C4506 "0.1uF" C0402 996.73,390.45 r270 top locked
C4509 "0.1uF" C0402 1162.73,395.45 r270 top locked
C4510 "10uF" C0603 1232.67,378.14 r0 top locked
C4700 "NC" C0402 687.06,503.83 r90 bottom locked
C4701 "8pF" C0402 650.64,503.83 r270 bottom locked
C4702 "4.7uF" C0603 405.67,245.14 r180 bottom locked
C4703 "4.7uF" C0603 541.67,494.37 r180 bottom locked
C4704 "1uF" C0402 677.73,233.5 r90 bottom locked
C4705 "0.1uF" C0402 480.73,233.5 r90 bottom locked
C4717 "0.1uF" C0402 1181.04,-1134.86 r0 bottom locked
C4718 "0.1uF" C0402 341.18,-1316 r90 bottom locked
C4719 "0.1uF" C0402 287.42,-1359.86 r180 top locked
D1 "NC/POWER" LED0805 1282.73,195.14 r180 top locked
D2 "NC/AU0511P1" C0402 -656.27,411.83 r270 top locked
D3 "NC/POWER" LED0805 1283.73,276.14 r180 top locked
D5 "SCHOTTKY" SOD123 1318.73,-1171.86 r270 top locked
D6 "SCHOTTKY" SOD123 1156.74,-1163.86 r90 top locked
D12 "SS14" SOD123 716.74,-1307.86 r180 top locked
D13 "SCHOTTKY" SOD123 1231.74,-1343.86 r180 top locked
D14 "AU0511P1" C0402 -1079.23,-390.86 r180 top locked
D15 "AU0511P1" C0402 -973.96,-212.14 r180 top locked
D16 "AU0511P1" C0402 -973.96,-458.78 r180 top locked
D17 "AU0511P1" C0402 -973.96,-423.54 r180 top locked
D18 "AU0511P1" C0402 -973.96,-388.31 r180 top locked
D19 "AU0511P1" C0402 -973.96,-282.61 r180 top locked
D20 "AU0511P1" C0402 -973.96,-247.37 r180 top locked
D21 "AU0511P1" C0402 -973.96,-494.01 r180 top locked
D26 "AU0511P1" C0402 -795.96,430.14 r0 top locked
D27 "AU0511P1" C0402 -1276.58,249.14 r180 top locked
D28 "AU0511P1" C0402 -1276.58,210.81 r180 top locked
D29 "AU0511P1" C0402 -795.96,239.14 r0 bottom locked
D30 "AU0561P1" C0402 34.73,291.45 r270 bottom locked
D31 "AU0561P1" C0402 -1.27,291.45 r270 bottom locked
D36 "AU0511P1" C0402 -38.27,291.45 r270 bottom locked
D37 "AU0511P1" C0402 106.73,291.45 r270 bottom locked
D38 "AU0511P1" C0402 -515.27,416 r270 top locked
D39 "BLUE" LED0603 -1337.81,-449.86 r180 top locked
D40 "RED" LED0603 -1339.27,-374.86 r180 top locked
DC1 "104" C0402 -720.44,-510.42 r0 bottom locked
DC2 "10uF" C0603 710,-982.56 r270 bottom locked
DC3 "1uF" C0402 -751.27,-389 r90 bottom locked
DC4 "1uF" C0402 -772.14,-5 r0 bottom locked
DC5 "104" C0402 -62.08,-154.53 r90 bottom locked
DC6 "104" C0402 -637,32 r270 bottom locked
DC7 "104" C0402 -254.01,-220.88 r270 top locked
DC8 "104" C0402 -773.13,42.14 r0 top locked
DC9 "104" C0402 -772.86,-4.86 r180 top locked
DC10 "1uF" C0402 -637.27,32.28 r270 top locked
DC11 "1uF" C0402 -577.14,96 r0 top locked
DC12 "10uF" C0603 -680.21,98.14 r180 top locked
DC13 "1uF" C0402 -62.08,-309.67 r90 bottom locked
DC14 "104" C0402 -62.08,-232.1 r270 bottom locked
DC15 "104" C0402 -750.13,-319.86 r0 bottom locked
DC16 "104" C0402 618.05,-969.66 r270 bottom locked
DC17 "104" C0402 -785.27,-483 r90 bottom locked
DC20 "104" C0402 -780.42,-188.05 r90 bottom locked
DC21 "104" C0402 -802.27,-69.72 r270 bottom locked
DC22 "104" C0402 -615.05,-510.42 r180 bottom locked
DC23 "1uF" C0402 -596.27,32.28 r270 top locked
DR1 "2K-1%" R0402 -773.58,83.14 r0 top locked
DR2 "240-1%" R0402 -715.27,35.66 r270 top locked
DR3 "100R" R0402 -799.27,-275.17 r270 bottom locked
DR4 "240-1%" R0402 -678.27,35.66 r270 top locked
DR5 "240-1%" R0402 -63.98,-508 r90 bottom locked
DR7 "2K-1%" R0402 -624.27,-210.95 r270 bottom locked
DU1 "LPDDR3_FBGA178" BGA178P0_8X0_65B13X11_5H1_13 -549.01,-267.02 r0 top locked
ED1 "NC/ESD9B5V" E0402N -770.41,-1360.86 r180 bottom locked
ED2 "NC/ESD9B5V" E0402N -528.13,-1361.86 r0 bottom locked
ED25 "AZ5725-01F" R0402 1196.04,-325.86 r180 bottom locked
ED26 "AZ5725-01F" R0402 1198.04,-474.86 r180 bottom locked
ED27 "AZ5725-01F" R0402 1197.42,-425.86 r180 bottom locked
ED28 "AZ5725-01F" R0402 550.53,-53.55 r270 bottom locked
ED29 "AZ5725-01F" R0402 590.13,-53.55 r270 bottom locked
ED30 "AZ5725-01F" R0402 412.73,28.45 r270 bottom locked
ED32 "AZ5725-01F" R0402 629.73,-53.55 r270 bottom locked
ED33 "AZ5725-01F" R0402 669.33,-53.55 r270 bottom locked
ED34 "AZ5725-01F" R0402 708.93,-53.55 r270 bottom locked
FB1 "600R-100M" L0402 -1015.27,79.28 r90 top locked
FB2 "600R-100M" L0402 -1088.63,79.63 r90 top locked
FB3 "0R" L0603 -796.2,-1244.01 r90 bottom locked
J3 "FPC4-PT1_25" FPC4-PT1_25-3_8X10H4_6B 1233.73,-398.86 r90 top locked
J8 "MICROSD/TF_SLOT" MICROSD_SLOT -1076.27,-344.86 r270 bottom locked
J9 "Touch_screen" FPC8-PT0.5-H1_9A 557.04,-40.86 r0 top locked
J4700 "OV2659" AYF333135 623.62,376.81 r180 bottom locked
J4702 "PJ342" PJ342 -1063.27,335.14 r0 bottom locked
L1 "1.0uH@2A DCR<0.1R" L4018 945.59,-960.42 r270 top locked
L2 "1.0uH@3A DCR<0.1R" L4018 551.41,-270.06 r90 top locked
L3 "1.0uH@3A DCR<0.1R" L4018 744.91,-270.06 r180 top locked
L4 "10uH" CD32 945.59,-1168.04 r270 top locked
L5 "1.0uH@3A DCR<0.1R" L4018 937.41,-272.24 r90 top locked
L6 "1.0uH@2A DCR<0.1R" L4018 544.41,-960.42 r270 top locked
L7 "1.0uH@2A DCR<0.1R" L4018 742.59,-960.42 r0 top locked
L9 "10uH@1A DCR<0.1R" L4018 742.59,-1168.04 r0 top locked
L10 "3.3uH@0.7A DCR<0.1R" L3518 -724.27,-806.86 r0 bottom locked
L11 "1.0uH@3A DCR<0.1R" CD32 540.41,-1168.04 r180 top locked
OD1 "SS24" SOD123 1245.73,163.13 r90 bottom locked
OL1 "2.2uH-DCR<0.1R-2A" CD43 1294.73,-49.68 r0 top locked
OLED1 "CON39-PT0_6H1_8B" CON39-PT0_6H1_8B 1320.73,-1088.86 r90 bottom locked
OU1 "MT3608" SOT23-6 1280.73,-56.5 r0 bottom locked
Q4 "WPM1481" DFN8P0_65B2_00X2_00H0_75 563.41,-1143.67 r180 bottom locked
Q7 "MMBT3904" SOT-23 367.41,-1003.86 r90 bottom locked
Q8 "MMBT3904" SOT-23 516.41,-1004.86 r90 bottom locked
Q17 "MMBT3904" SOT-23 -1197.27,-308.36 r180 top locked
Q18 "MMBT3904" SOT-23 -1197.27,-474.36 r180 top locked
R5 "0R" R0402 145.31,-593 r180 bottom locked
R6 "2K" R0402 -2.5,-602.17 r270 bottom locked
R7 "2K" R0402 -37.75,-602.17 r270 bottom locked
R8 "200K-1%" R0402 68,-602.17 r270 bottom locked
R9 "3.3K" 0805 962.41,-1287.23 r270 bottom locked
R10 "10K" 0805 1034.41,-1287.23 r90 bottom locked
R11 "NC/1K" R0402 1324.73,229.14 r180 bottom locked
R12 "1K" R0402 472.72,-504.24 r180 bottom locked
R14 "NC/0R" R0402 455.75,-540.48 r180 top locked
R17 "NC/1K" R0402 -694.27,411.83 r270 top locked
R18 "NC/10K" R0402 1321.42,271.71 r0 bottom locked
R19 "NC/10K" R0402 1022.41,-330.55 r90 bottom locked
R22 "1M-1%" R0402 1365.73,-14.55 r270 bottom locked
R23 "130K-1%" R0402 1365.73,-90.17 r270 bottom locked
R24 "10K" R0402 54,-833 r0 bottom locked
R25 "NC/0R" R0402 54.69,-797 r180 bottom locked
R26 "NC/0R" R0402 -18.95,-798.97 r180 bottom locked
R27 "10K" R0402 -18.95,-836.91 r180 bottom locked
R28 "33R" R0402 32.75,-602.17 r90 bottom locked
R29 "10K" R0402 -18.95,-874.86 r180 bottom locked
R33 "2K" R0402 650.41,-886.55 r90 bottom locked
R75 "10K" R0402 1181.04,-1246.86 r180 bottom locked
R85 "2K7" R0402 1183.04,-933.63 r0 bottom locked
R86 "4K7" R0402 726.01,-1287.55 r270 bottom locked
R87 "22R-1%" R0603 1166.67,-836.63 r180 bottom locked
R88 "4K7" R0402 766.81,-1287.55 r270 bottom locked
R89 "17K5" R0402 807.61,-1287.55 r90 bottom locked
R90 "470R" R0402 445.41,-878.17 r270 bottom locked
R91 "4K7" R0402 644.41,-1287.55 r90 bottom locked
R92 "10K" R0402 399.41,-878.55 r90 bottom locked
R93 "47K" R0402 340.41,-1125.55 r90 bottom locked
R121 "2R2" R0603 -1066.33,-289.86 r0 top locked
R122 "10K" R0402 -973.96,-317.84 r0 top locked
R123 "47K" R0402 -973.96,-529.25 r0 top locked
R125 "33R" R0402 -108,-602.69 r270 bottom locked
R126 "10K" R0402 130.73,-1162.17 r270 top locked
R127 "100K" R0402 1177.04,-865.61 r0 top locked
R128 "10K" R0402 2.04,-1318.86 r0 bottom locked
R129 "10R" R0402 463.73,28.83 r270 bottom locked
R132 "8K2-1%" R0402 1260.73,-459.17 r270 bottom locked
R133 "10K-1%" R0402 1313.66,-478.86 r0 bottom locked
R134 "11K-1%" R0402 1313.66,-514.86 r180 bottom locked
R135 "13K-1%" R0402 1242.42,-514.86 r180 bottom locked
R136 "47K" R0402 141.73,291.45 r270 bottom locked
R137 "6K8-1%" R0402 -24.96,237.14 r0 bottom locked
R138 "15K/NC" R0402 1334.04,-785.86 r0 bottom locked
R139 "100K" R0402 88.42,237.14 r180 bottom locked
R140 "1K" R0402 70.73,291.45 r90 bottom locked
R144 "2k" R0402 -1276.58,134.14 r180 top locked
R149 "0R" R0402 -795.96,392.54 r180 top locked
R150 "22R" R0402 -1051.61,9.83 r270 top locked
R151 "22R" R0402 -978.27,9.83 r270 top locked
R152 "0R" R0402 890.41,-884.55 r90 bottom locked
R162 "2K" R0402 989.1,-532.86 r0 bottom locked
R167 "NC" R0402 -409.96,-1367.86 r180 top locked
R168 "0R" R0402 -334.58,-1366.86 r180 top locked
R169 "10M-1%" R0402 1031.98,-766.86 r0 top locked
R173 "33K" R0402 -870.96,-902.86 r0 bottom locked
R174 "33K" R0402 -870.96,-940.86 r0 bottom locked
R176 "33K" R0402 -870.96,-1016.86 r0 bottom locked
R177 "33K" R0402 -870.96,-1054.86 r0 bottom locked
R178 "33K" R0402 -870.96,-1092.86 r0 bottom locked
R179 "NC/10K" R0402 -1019.58,-901.12 r180 bottom locked
R180 "10K" R0402 -1019.58,-936.7 r180 bottom locked
R181 "10K" R0402 -1019.58,-972.28 r180 bottom locked
R182 "NC/10K" R0402 -1019.58,-1007.86 r180 bottom locked
R183 "NC/560k" R0402 -544,-1107 r270 bottom locked
R184 "0R" R0402 -600.96,-1088.86 r180 bottom locked
R185 "0R" R0402 -600.96,-1125.86 r0 bottom locked
R186 "100R" R0402 -565.31,-1048.69 r0 bottom locked
R187 "100K" R0402 -683.27,-1020.17 r270 bottom locked
R188 "10K" R0402 -888.27,-779.17 r90 bottom locked
R190 "NC/100K" R0402 -1051.58,-755.86 r0 bottom locked
R191 "NC/100K" R0402 -647.27,-1020.17 r90 bottom locked
R192 "0R" R0402 -957.27,-789.55 r270 bottom locked
R193 "100K" R0402 -965,-992 r270 bottom locked
R194 "100K" R0402 -1052.58,-718.86 r180 bottom locked
R195 "33R" R0402 -870.96,-978.86 r180 bottom locked
R196 "0R" R0402 -853.27,-779.55 r90 bottom locked
R318 "0R" R0402 -1078.58,-1305.86 r0 top locked
R319 "0R01-1%" R0805 422.41,-1164.23 r90 bottom locked
R325 "NC" R0402 -54,-924 r180 bottom locked
R326 "NC" R0402 -357.69,-878 r0 bottom locked
R328 "NC" R0402 211,88.69 r90 top locked
R329 "0R" R0402 248,88.69 r90 top locked
R463 "0R" R0805 435,-330.37 r270 bottom locked
R464 "0R\200K" R0402 -888.27,-850.17 r270 bottom locked
R465 "200K/NC" R0402 -853.27,-850.17 r270 bottom locked
R466 "NC" R0402 -993.27,-789.55 r90 bottom locked
R473 "2k" R0402 686.75,-886.55 r90 bottom locked
R474 "2k" R0402 723.08,-886.55 r90 bottom locked
R475 "1K" R0402 -1082.61,-438.86 r180 top locked
R476 "1K" R0402 -1082.61,-171.46 r180 top locked
R477 "10K" R0402 -1082.61,-207.86 r180 top locked
R478 "47K" R0402 -1082.61,-244.86 r180 top locked
R479 "10K" R0402 -1082.61,-480.36 r0 top locked
R480 "47K" R0402 -1082.61,-521.86 r0 top locked
R481 "10K" R0402 168.73,-1162.17 r90 top locked
R482 "NC/0R" R0402 120.73,-1340.55 r270 top locked
R483 "NC/0R" R0402 82.73,-1340.55 r270 top locked
R484 "0R" R0402 92.73,-1162.17 r270 bottom locked
R485 "NC" R0402 92.73,-1162.17 r90 top locked
R486 "0R" R0402 -7.27,-1162.17 r270 top locked
R487 "0R" R0402 -72.27,-1342.55 r90 bottom locked
R488 "0R" R0402 -155.27,-1346.17 r270 top locked
R489 "10K" R0402 -155.27,-1342.17 r270 bottom locked
R490 "10K" R0402 -165.27,-1184.17 r90 top locked
R491 "10K" R0402 -202.55,-1184.17 r90 top locked
R497 "2K" R0402 -106.31,-731 r0 bottom locked
R498 "2K" R0402 -373.69,-733 r180 bottom locked
R504 "100K" R0402 1181.04,-1284.86 r0 bottom locked
R505 "100K" R0402 1181.04,-1208.86 r0 bottom locked
R506 "62K" R0402 -556.89,-1239.08 r0 bottom locked
R507 "62K" R0402 -556.89,-1202.08 r0 bottom locked
R517 "0R" R0402 29.73,-1162.17 r270 top locked
R518 "0R" R0402 -45.27,-1162.17 r270 top locked
R519 "NC/0R" R0402 29.73,-1162.17 r270 bottom locked
R520 "NC/0R" R0402 -45.27,-1162.17 r270 bottom locked
R521 "NC/0R" R0402 -144.58,-1246.86 r180 top locked
R522 "NC/0R" R0402 -144.58,-1284.86 r180 top locked
R1003 "22R-1%" R0603 1166.67,-889.63 r180 bottom locked
R1006 "NC/10K" R0402 -104.58,-693.25 r180 bottom locked
R1007 "100K" R0402 -104.58,-657.25 r0 bottom locked
R1008 "10K" R0402 1181.04,-1322.86 r180 bottom locked
R1009 "10K" R0402 1181.04,-1170.86 r180 bottom locked
R1010 "100R" R0402 -1354.96,-314.86 r180 top locked
R4500 "NC" R0402 1161.73,319.83 r90 top locked
R4700 "4K7" R0402 468.73,503.83 r270 bottom locked
R4701 "4K7" R0402 429.37,503.83 r270 bottom locked
R4702 "33R" R0402 723.48,503.83 r90 bottom locked
R4703 "33R" R0402 614.23,503.83 r90 bottom locked
R4704 "10K" R0402 520.13,233.5 r270 bottom locked
R4705 "NC/0R" R0402 638.33,233.5 r90 bottom locked
R4706 "0R" R0402 598.93,233.5 r90 bottom locked
R4707 "NC/4K7" R0402 358.42,356.98 r180 bottom locked
R4708 "4K7/NC" R0402 358.42,393.98 r180 bottom locked
R5117 "0R" R0402 358.42,430.98 r0 bottom locked
R5118 "0R" R0402 559.53,233.5 r90 bottom locked
R5119 "1M" R0402 -556.89,-1313.08 r180 bottom locked
R5120 "100K" R0402 -556.89,-1276.08 r180 bottom locked
R5121 "0-04" R0402 -695.96,-1359.86 r0 top locked
R5122 "0-04" R0402 -610.58,-1358.86 r180 top locked
R5123 "NC/100K" R0402 -629.89,-1278.08 r0 bottom locked
R5124 "100R" R0402 -1354.96,-502.86 r180 top locked
R5132 "0R、" R0402 212.04,-1298.86 r0 bottom locked
R5133 "0R" R0402 342.73,-1246.17 r270 bottom locked
R5134 "NC/0R" R0402 211.04,-1262.86 r0 bottom locked
R5135 "NC/0R" R0402 212.04,-1226.86 r0 bottom locked
R5136 "10K" R0402 286.04,-1298.86 r180 bottom locked
SHIELD12_1 "CON5" TEST2 -566.27,-781 r270 bottom locked (schematic designator SHIELD6)
SHIELD12_1 "CON5" TEST2 -847.27,-158 r270 bottom locked (schematic designator SHIELD6)
SHIELD12_1 "CON5" TEST2 141,198.14 r180 bottom locked (schematic designator SHIELD6)
SHIELD12_1 "CON5" TEST2 -494,198.14 r180 bottom locked (schematic designator SHIELD6)
SHIELD12_1 "CON5" TEST2 716,-1369.86 r180 bottom locked (schematic designator SHIELD6)
SHIELD12_1 "CON5" TEST2 1087.73,-349 r90 bottom locked (schematic designator SHIELD6)
SHIELD12_1 "CON5" TEST2 1087.73,-1145 r90 bottom locked (schematic designator SHIELD6)
SHIELD12_1 "CON5" TEST2 723,-146.86 r0 bottom locked (schematic designator SHIELD6)
SHIELD12_1 "CON5" TEST2 383.73,36 r270 bottom locked (schematic designator SHIELD6)
SHIELD12_1 "CON5" TEST2 383.73,-819 r270 bottom locked (schematic designator SHIELD6)
SHIELD12_1 "CON5" TEST2 -110,-1099.86 r180 bottom locked (schematic designator SHIELD6)
SHIELD12_1 "CON5" TEST2 -902,-597.86 r180 bottom locked (schematic designator SHIELD6)
SHIELD12_1 "CON5" TEST2 -607.27,-898 r90 bottom locked (schematic designator SHIELD6)
SHIELD12_1 "CON5" TEST2 -1191.27,-949 r90 bottom locked (schematic designator SHIELD6)
SW8 "UBOOT" SW4_SMD -450.85,484.76 r180 bottom locked
SW9 "UBOOT" SW4_SMD -718.78,484.44 r180 bottom locked
T35 "TEST" TP40_SMD 1165.73,-1366.86 r90 bottom locked
TP41 "TEST" TP_SMD 1269.73,-790.86 r270 bottom locked
TP42 "TEST" TP_SMD 1194.73,-778.86 r270 bottom locked
TP43 "TEST" TP_SMD 1110.73,-1367.36 r90 bottom locked
TP44 "TEST" TP_SMD 1225.73,-1367.36 r90 bottom locked
TP47 "ENTER" TP_SMD 1254.73,-573.86 r90 bottom locked
TP50 "HS-MIC" TP_SMD -1242.28,78.14 r90 bottom locked
TP51 "HPOUTL" TP_SMD -1014.94,27.52 r90 bottom locked
TP52 "HPOUTR" TP_SMD -1088.27,28.14 r90 bottom locked
TP53 "MIC2N-N" TP_SMD -813.65,279.74 r90 bottom locked
TP54 "HPOUTFB" TP_SMD -813.65,354.94 r90 bottom locked
TP61 "PWRON" TP_SMD 391.73,-502.86 r90 bottom locked
TP62 "GND" TP_SMD 1061.41,-598.86 r90 bottom locked
TP67 "ENTER" TP_SMD 1315.73,-574.86 r90 bottom locked
TP68 "MIC_P" TP_SMD -689.2,-1359.08 r270 bottom locked
TP69 "MIC_P" TP_SMD -606.2,-1359.08 r270 bottom locked
TP70 "MIC_P" TP_SMD -1263,-1024 r0 bottom locked
TP71 "MIC_P" TP_SMD -1264,-1121 r0 bottom locked
TP74 "HPOUTFB" TP_SMD 1173.73,-527.86 r0 bottom locked
TST "NC" TP_SMD -188.27,-1197.86 r0 bottom locked
U1 "H8" BGA345P0_65B14X14 51.03,-256.92 r0 top locked
U6 "SP4446" sot23-5 947.41,-1138.86 r270 bottom locked
U11 "AP3032/SY7200A" SOT23-6 743.41,-1174.86 r270 bottom locked
U14 "IA6005-18S25F" SOT23_5H14A 923.73,427.14 r90 bottom locked
U15 "IA6004-18S25F" SOT23_5H14A 1316.73,-948.86 r270 top locked
U19 "SY6280" SOT23-5 34.73,288.14 r270 top locked
U24 "AP6210/AP6181/8723BS" QFN44P0_90B12_00X12_00H1_50 -898.91,-900.69 r90 top locked
U28 "AXP818-BGA218" BGA218_P0_65B11X11 737.63,-612.04 r180 top locked
U29 "EMMC5_0_BGA169" BGA169P0_50B12_00X16_00H1_00 -132.64,-827.86 r90 top locked
U30 "NC/MPU6515A" QFN24-3X3 -345.27,-1248.86 r270 top locked
U100 "BMC156" BGA156 120.73,-1253.86 r0 top locked
U101 "BMG160" BGA160 -27.27,-1272.86 r0 top locked
U103 "LM4890" MSOP8-PT1-27A -644.27,-1270.86 r180 top locked
U1000 "ADW101" SOT23-6 -241,-695 r270 bottom locked
U4500 "PT5108E23-28/RT9013-28B" SOT23_5H14A 1078.23,427.14 r90 bottom locked
U4502 "NC/PT5108E23-15/RT9013-15B" SOT23_5H14A 1232.73,427.14 r90 bottom locked
U4503 "AK09911" AK09911 -213.21,-1269.11 r0 top locked
U4505 "BMI160" BMI160 281.73,-1253.86 r0 top locked
USB1 "MIRCO_USB_5P" MIRCO_USB-5PH3A_DIP 28.73,473.14 r180 bottom locked
X1 "24M-20pF-10PPM" CRY-TSX3225 172,-719 r90 bottom locked
X2 "32768" XCOL-SMD 1023.66,-563.86 r90 top locked
Y1 "26MHz 10ppm" CRY-TSX3225 -468,-1085 r180 bottom locked

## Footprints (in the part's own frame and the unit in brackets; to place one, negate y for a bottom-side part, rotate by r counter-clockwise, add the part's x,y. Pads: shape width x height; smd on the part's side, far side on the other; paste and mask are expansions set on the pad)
0805 [mm]
  rect 1x1 smd: 1(-1,0) 2(1,0)
  silkscreen extent -1.8,-0.8 1.8,0.8
AK09911 [mil] "AK09911_MS1526_E-01"
  round 9.06 smd: A1(-15.76,15.75) A2(-0.06,15.75) A3(15.74,15.75) B1(-15.76,0.05) B3(15.74,0.05) C1(-15.76,-15.75) C2(-0.06,-15.75) C3(15.74,-15.75)
  silkscreen extent -24,-24 23,28
AYF333135 [mm]
  rect 0.3x0.55 smd: 1(4.5,-1.38) 3(3.9,-1.38) 5(3.3,-1.38) 7(2.7,-1.38) 9(2.1,-1.38) 11(1.5,-1.38) 13(0.9,-1.38) 15(0.3,-1.38) 17(-0.3,-1.38) 19(-0.9,-1.38) 21(-1.5,-1.38) 23(-2.1,-1.38) 25(-2.7,-1.38) 27(-3.3,-1.38) 29(-3.9,-1.38) 31(-4.5,-1.38)
  rect 0.3x0.45 smd: 2(4.2,1.38) 4(3.6,1.38) 6(3,1.38) 8(2.4,1.38) 10(1.8,1.38) 12(1.2,1.38) 14(0.6,1.38) 16(0,1.38) 18(-0.6,1.38) 20(-1.2,1.38) 22(-1.8,1.38) 24(-2.4,1.38) 26(-3,1.38) 28(-3.6,1.38) 30(-4.2,1.38)
  silkscreen extent -5.5,-2.16 5.5,1.5
BGA156 [mm]
  rect 0.35x0.3 smd: 1(-0.78,0.75) 2(-0.78,0.25) 3(-0.78,-0.25) 4(-0.78,-0.75) 7(0.78,-0.75) 8(0.78,-0.25) 9(0.78,0.25) 10(0.78,0.75)
  rect 0.3x0.35 smd: 5(-0.25,-0.78) 6(0.25,-0.78) 11(0.25,0.78) 12(-0.25,0.78)
  silkscreen extent -1.63,-1.1 1.1,1.1
BGA160 [mm]
  rect 0.6x0.28 smd: 1(-1.201,1) 2(-1.201,0.5) 3(-1.201,0) 4(-1.201,-0.5) 5(-1.201,-1) 7(1.202,-1) 8(1.202,-0.5) 9(1.202,0) 10(1.202,0.5) 11(1.202,1)
  rect 0.28x0.6 smd: 6(0,-1.201) 12(0,1.202)
  silkscreen extent -2.37,-1.65 1.68,1.68
BGA169P0_50B12_00X16_00H1_00 [mil] "BGA169P0_50B12_00X16_00H1_00"
  round 9.84 smd: A4(-68.9,265.75) A6(-29.53,265.75) A9(29.53,265.75) A11(68.9,265.75) AA1(-127.95,-127.95) AA2(-108.27,-127.95) AA3(-88.58,-127.95) AA4(-68.9,-127.95) AA5(-49.21,-127.95) AA6(-29.53,-127.95) AA7(-9.84,-127.95) AA8(9.84,-127.95) AA9(29.53,-127.95) AA10(49.21,-127.95) AA11(68.9,-127.95) AA12(88.58,-127.95) AA13(108.27,-127.95) AA14(127.95,-127.95) AE1(-127.95,-206.69) AE14(127.95,-206.69) AG2(-108.27,-246.06) AG13(108.27,-246.06) AH4(-68.9,-265.75) AH6(-29.53,-265.75) AH9(29.53,-265.75) AH11(68.9,-265.75) B2(-108.27,246.06) B13(108.27,246.06) D1(-127.95,206.69) D14(127.95,206.69) H1(-127.95,127.95) H3(-88.58,127.95) H4(-68.9,127.95) H5(-49.21,127.95) H6(-29.53,127.95) H8(9.84,127.95) H9(29.53,127.95) H10(49.21,127.95) H11(68.9,127.95) H12(88.58,127.95) H13(108.27,127.95) H14(127.95,127.95) J1(-127.95,108.27) J2(-108.27,108.27) J3(-88.58,108.27) J4(-68.9,108.27) J5(-49.21,108.27) J6(-29.53,108.27) J7(-9.84,108.27) J8(9.84,108.27) J9(29.53,108.27) J10(49.21,108.27) J11(68.9,108.27) J12(88.58,108.27) J13(108.27,108.27) J14(127.95,108.27) K2(-108.27,88.58) K3(-88.58,88.58) K4(-68.9,88.58) K6(-29.53,88.58) K7(-9.84,88.58) K8(9.84,88.58) K9(29.53,88.58) K10(49.21,88.58) K11(68.9,88.58) K12(88.58,88.58) K13(108.27,88.58) K14(127.95,88.58) L1(-127.95,68.9) L2(-108.27,68.9) L3(-88.58,68.9) L12(88.58,68.9) L13(108.27,68.9) L14(127.95,68.9) M1(-127.95,49.21) M2(-108.27,49.21) M3(-88.58,49.21) M5(-49.21,49.21) M6(-29.53,49.21) M7(-9.84,49.21) M8(9.84,49.21) M9(29.53,49.21) M10(49.21,49.21) M12(88.58,49.21) M13(108.27,49.21) M14(127.95,49.21) N1(-127.95,29.53) N2(-108.27,29.53) N3(-88.58,29.53) N5(-49.21,29.53) N10(49.21,29.53) N12(88.58,29.53) N13(108.27,29.53) N14(127.95,29.53) P1(-127.95,9.84) P2(-108.27,9.84) P3(-88.58,9.84) P5(-49.21,9.84) P10(49.21,9.84) P12(88.58,9.84) P13(108.27,9.84) P14(127.95,9.84) R1(-127.95,-9.84) R2(-108.27,-9.84) R3(-88.58,-9.84) R5(-49.21,-9.84) R10(49.21,-9.84) R12(88.58,-9.84) R13(108.27,-9.84) R14(127.95,-9.84) T1(-127.95,-29.53) T2(-108.27,-29.53) T3(-88.58,-29.53) T5(-49.21,-29.53) T10(49.21,-29.53) T12(88.58,-29.53) T13(108.27,-29.53) T14(127.95,-29.53) U1(-127.95,-49.21) U2(-108.27,-49.21) U3(-88.58,-49.21) U5(-49.21,-49.21) U6(-29.53,-49.21) U7(-9.84,-49.21) U8(9.84,-49.21) U9(29.53,-49.21) U10(49.21,-49.21) U12(88.58,-49.21) U13(108.27,-49.21) U14(127.95,-49.21) V1(-127.95,-68.9) V2(-108.27,-68.9) V3(-88.58,-68.9) V12(88.58,-68.9) V13(108.27,-68.9) V14(127.95,-68.9) W1(-127.95,-88.58) W2(-108.27,-88.58) W3(-88.58,-88.58) W4(-68.9,-88.58) W5(-49.21,-88.58) W6(-29.53,-88.58) W7(-9.84,-88.58) W8(9.84,-88.58) W9(29.53,-88.58) W10(49.21,-88.58) W11(68.9,-88.58) W12(88.58,-88.58) W13(108.27,-88.58) W14(127.95,-88.58) Y2(-108.27,-108.27) Y3(-88.58,-108.27) Y4(-68.9,-108.27) Y5(-49.21,-108.27) Y6(-29.53,-108.27) Y7(-9.84,-108.27) Y8(9.84,-108.27) Y9(29.53,-108.27) Y10(49.21,-108.27) Y11(68.9,-108.27) Y12(88.58,-108.27) Y13(108.27,-108.27) Y14(127.95,-108.27)
  silkscreen extent -237,-315 236,336
BGA178P0_8X0_65B13X11_5H1_13 [mm] "BGA178P0_8X0_65B13X11_5H1_13"
  round 0.3 smd: A1(-4.8,5.2) A2(-4,5.2) A3(-3.2,5.2) A4(-2.4,5.2) A5(-1.6,5.2) A6(-0.8,5.2) A8(0.8,5.2) A9(1.6,5.2) A10(2.4,5.2) A11(3.2,5.2) A12(4,5.2) A13(4.8,5.2) B1(-4.8,4.55) B2(-4,4.55) B3(-3.2,4.55) B4(-2.4,4.55) B5(-1.6,4.55) B6(-0.8,4.55) B8(0.8,4.55) B9(1.6,4.55) B10(2.4,4.55) B11(3.2,4.55) B12(4,4.55) B13(4.8,4.55) C2(-4,3.9) C3(-3.2,3.9) C4(-2.4,3.9) C5(-1.6,3.9) C6(-0.8,3.9) C8(0.8,3.9) C9(1.6,3.9) C10(2.4,3.9) C11(3.2,3.9) C12(4,3.9) D2(-4,3.25) D3(-3.2,3.25) D4(-2.4,3.25) D5(-1.6,3.25) D6(-0.8,3.25) D8(0.8,3.25) D9(1.6,3.25) D10(2.4,3.25) D11(3.2,3.25) D12(4,3.25) E2(-4,2.6) E3(-3.2,2.6) E4(-2.4,2.6) E5(-1.6,2.6) E6(-0.8,2.6) E8(0.8,2.6) E9(1.6,2.6) E10(2.4,2.6) E11(3.2,2.6) E12(4,2.6) F2(-4,1.95) F3(-3.2,1.95) F4(-2.4,1.95) F5(-1.6,1.95) F6(-0.8,1.95) F8(0.8,1.95) F9(1.6,1.95) F10(2.4,1.95) F11(3.2,1.95) F12(4,1.95) G2(-4,1.3) G3(-3.2,1.3) G4(-2.4,1.3) G5(-1.6,1.3) G6(-0.8,1.3) G8(0.8,1.3) G9(1.6,1.3) G10(2.4,1.3) G11(3.2,1.3) G12(4,1.3) H2(-4,0.65) H3(-3.2,0.65) H4(-2.4,0.65) H5(-1.6,0.65) H6(-0.8,0.65) H8(0.8,0.65) H9(1.6,0.65) H10(2.4,0.65) H11(3.2,0.65) H12(4,0.65) J2(-4,0) J3(-3.2,0) J4(-2.4,0) J5(-1.6,0) J6(-0.8,0) J8(0.8,0) J9(1.6,0) J10(2.4,0) J11(3.2,0) J12(4,0) K2(-4,-0.65) K3(-3.2,-0.65) K4(-2.4,-0.65) K5(-1.6,-0.65) K6(-0.8,-0.65) K8(0.8,-0.65) K9(1.6,-0.65) K10(2.4,-0.65) K11(3.2,-0.65) K12(4,-0.65) L2(-4,-1.3) L3(-3.2,-1.3) L4(-2.4,-1.3) L5(-1.6,-1.3) L6(-0.8,-1.3) L8(0.8,-1.3) L9(1.6,-1.3) L10(2.4,-1.3) L11(3.2,-1.3) L12(4,-1.3) M2(-4,-1.95) M3(-3.2,-1.95) M4(-2.4,-1.95) M5(-1.6,-1.95) M6(-0.8,-1.95) M8(0.8,-1.95) M9(1.6,-1.95) M10(2.4,-1.95) M11(3.2,-1.95) M12(4,-1.95) N2(-4,-2.6) N3(-3.2,-2.6) N4(-2.4,-2.6) N5(-1.6,-2.6) N6(-0.8,-2.6) N8(0.8,-2.6) N9(1.6,-2.6) N10(2.4,-2.6) N11(3.2,-2.6) N12(4,-2.6) P2(-4,-3.25) P3(-3.2,-3.25) P4(-2.4,-3.25) P5(-1.6,-3.25) P6(-0.8,-3.25) P8(0.8,-3.25) P9(1.6,-3.25) P10(2.4,-3.25) P11(3.2,-3.25) P12(4,-3.25) R2(-4,-3.9) R3(-3.2,-3.9) R4(-2.4,-3.9) R5(-1.6,-3.9) R6(-0.8,-3.9) R8(0.8,-3.9) R9(1.6,-3.9) R10(2.4,-3.9) R11(3.2,-3.9) R12(4,-3.9) T1(-4.8,-4.55) T2(-4,-4.55) T3(-3.2,-4.55) T4(-2.4,-4.55) T5(-1.6,-4.55) T6(-0.8,-4.55) T8(0.8,-4.55) T9(1.6,-4.55) T10(2.4,-4.55) T11(3.2,-4.55) T12(4,-4.55) T13(4.8,-4.55) U1(-4.8,-5.2) U2(-4,-5.2) U3(-3.2,-5.2) U4(-2.4,-5.2) U5(-1.6,-5.2) U6(-0.8,-5.2) U8(0.8,-5.2) U9(1.6,-5.2) U10(2.4,-5.2) U11(3.2,-5.2) U12(4,-5.2) U13(4.8,-5.2)
  silkscreen extent -6.97,-5.75 6.5,5.75
BGA218_P0_65B11X11 [mm] "BGA218_P0_65B11X11"
  round 0.3 smd: A1(-4.9,4.9) A2(-4.25,4.9) A3(-3.6,4.9) A4(-2.95,4.9) A5(-2.3,4.9) A6(-1.65,4.9) A7(-1,4.9) A8(-0.35,4.9) A9(0.3,4.9) A10(0.95,4.9) A11(1.6,4.9) B1(-4.9,4.25) B2(-4.25,4.25) B3(-3.6,4.25) B4(-2.95,4.25) B5(-2.3,4.25) B6(-1.65,4.25) B7(-1,4.25) B8(-0.35,4.25) B9(0.3,4.25) B10(0.95,4.25) C1(-4.9,3.6) C2(-4.25,3.6) C3(-3.6,3.6) C4(-2.95,3.6) C5(-2.3,3.6) C6(-1.65,3.6) C7(-1,3.6) C8(-0.35,3.6) C9(0.3,3.6) C12(2.25,3.6) C14(3.55,3.6) D1(-4.9,2.95) D2(-4.25,2.95) D3(-3.6,2.95) D4(-2.95,2.95) D5(-2.3,2.95) D6(-1.65,2.95) D7(-1,2.95) D8(-0.35,2.95) D12(2.25,2.95) D14(3.55,2.95) D15(4.2,2.95) D16(4.85,2.95) E1(-4.9,2.3) E2(-4.25,2.3) E3(-3.6,2.3) E4(-2.95,2.3) E5(-2.3,2.3) E7(-1,2.3) E9(0.3,2.3) E10(0.95,2.3) E12(2.25,2.3) E15(4.2,2.3) E16(4.85,2.3) F1(-4.9,1.65) F2(-4.25,1.65) F3(-3.6,1.65) F4(-2.95,1.65) F5(-2.3,1.65) F6(-1.65,1.65) F7(-1,1.65) F8(-0.35,1.65) F10(0.95,1.65) F11(1.6,1.65) F12(2.25,1.65) F13(2.9,1.65) F14(3.55,1.65) F15(4.2,1.65) F16(4.85,1.65) G1(-4.9,1) G2(-4.25,1) G3(-3.6,1) G4(-2.95,1) G5(-2.3,1) G6(-1.65,1) G7(-1,1) G8(-0.35,1) G9(0.3,1) G10(0.95,1) G11(1.6,1) G12(2.25,1) G13(2.9,1) G14(3.55,1) G15(4.2,1) G16(4.85,1) H1(-4.9,0.35) H2(-4.25,0.35) H3(-3.6,0.35) H4(-2.95,0.35) H5(-2.3,0.35) H6(-1.65,0.35) H7(-1,0.35) H8(-0.35,0.35) H9(0.3,0.35) H10(0.95,0.35) H11(1.6,0.35) H12(2.25,0.35) H13(2.9,0.35) H14(3.55,0.35) H15(4.2,0.35) H16(4.85,0.35) J1(-4.9,-0.3) J2(-4.25,-0.3) J3(-3.6,-0.3) J5(-2.3,-0.3) J6(-1.65,-0.3) J7(-1,-0.3) J8(-0.35,-0.3) J9(0.3,-0.3) J10(0.95,-0.3) J11(1.6,-0.3) J12(2.25,-0.3) J13(2.9,-0.3) J14(3.55,-0.3) J15(4.2,-0.3) J16(4.85,-0.3) K1(-4.9,-0.95) K2(-4.25,-0.95) K6(-1.65,-0.95) K7(-1,-0.95) K8(-0.35,-0.95) K9(0.3,-0.95) K10(0.95,-0.95) K11(1.6,-0.95) K12(2.25,-0.95) K13(2.9,-0.95) K14(3.55,-0.95) K15(4.2,-0.95) K16(4.85,-0.95) L1(-4.9,-1.6) L2(-4.25,-1.6) L5(-2.3,-1.6) L6(-1.65,-1.6) L7(-1,-1.6) L8(-0.35,-1.6) L9(0.3,-1.6) L10(0.95,-1.6) L11(1.6,-1.6) L12(2.25,-1.6) L13(2.9,-1.6) L14(3.55,-1.6) L15(4.2,-1.6) L16(4.85,-1.6) M1(-4.9,-2.25) M2(-4.25,-2.25) M5(-2.3,-2.25) M6(-1.65,-2.25) M7(-1,-2.25) M8(-0.35,-2.25) M9(0.3,-2.25) M10(0.95,-2.25) M11(1.6,-2.25) M12(2.25,-2.25) M13(2.9,-2.25) M14(3.55,-2.25) M15(4.2,-2.25) M16(4.85,-2.25) N1(-4.9,-2.9) N2(-4.25,-2.9) N4(-2.95,-2.9) N6(-1.65,-2.9) N7(-1,-2.9) N8(-0.35,-2.9) N9(0.3,-2.9) N10(0.95,-2.9) N11(1.6,-2.9) N12(2.25,-2.9) N13(2.9,-2.9) N14(3.55,-2.9) N15(4.2,-2.9) N16(4.85,-2.9) P1(-4.9,-3.55) P2(-4.25,-3.55) P4(-2.95,-3.55) P5(-2.3,-3.55) P6(-1.65,-3.55) P7(-1,-3.55) P8(-0.35,-3.55) P9(0.3,-3.55) P10(0.95,-3.55) P11(1.6,-3.55) P12(2.25,-3.55) P13(2.9,-3.55) P14(3.55,-3.55) P15(4.2,-3.55) P16(4.85,-3.55) R1(-4.9,-4.2) R2(-4.25,-4.2) R4(-2.95,-4.2) R5(-2.3,-4.2) R6(-1.65,-4.2) R7(-1,-4.2) R8(-0.35,-4.2) R9(0.3,-4.2) R10(0.95,-4.2) R11(1.6,-4.2) R12(2.25,-4.2) R13(2.9,-4.2) R14(3.55,-4.2) R15(4.2,-4.2) R16(4.85,-4.2) T1(-4.9,-4.85) T2(-4.25,-4.85) T3(-3.6,-4.85) T4(-2.95,-4.85) T5(-2.3,-4.85) T6(-1.65,-4.85) T7(-1,-4.85) T8(-0.35,-4.85) T9(0.3,-4.85) T10(0.95,-4.85) T11(1.6,-4.85) T12(2.25,-4.85) T13(2.9,-4.85) T14(3.55,-4.85) T15(4.2,-4.85) T16(4.85,-4.85)
  silkscreen extent -5.53,-5.47 5.47,5.53
BGA345P0_65B14X14 [mm] "BGA345P0_65B14X14"
  round 0.3 smd: A1(-6.496,6.526) A2(-5.846,6.526) A3(-5.196,6.526) A4(-4.546,6.526) A6(-3.246,6.526) A7(-2.596,6.526) A9(-1.296,6.526) A10(-0.646,6.526) A12(0.654,6.526) A13(1.304,6.526) A15(2.604,6.526) A16(3.254,6.526) A18(4.554,6.526) A19(5.204,6.526) A20(5.854,6.526) A21(6.504,6.526) AA1(-6.496,-6.474) AA2(-5.846,-6.474) AA3(-5.196,-6.474) AA4(-4.546,-6.474) AA6(-3.246,-6.474) AA7(-2.596,-6.474) AA9(-1.296,-6.474) AA10(-0.646,-6.474) AA12(0.654,-6.474) AA13(1.304,-6.474) AA15(2.604,-6.474) AA16(3.254,-6.474) AA18(4.554,-6.474) AA19(5.204,-6.474) AA20(5.854,-6.474) AA21(6.504,-6.474) B1(-6.496,5.876) B2(-5.846,5.876) B3(-5.196,5.876) B4(-4.546,5.876) B5(-3.896,5.876) B6(-3.246,5.876) B7(-2.596,5.876) B8(-1.946,5.876) B9(-1.296,5.876) B10(-0.646,5.876) B11(0.004,5.876) B12(0.654,5.876) B13(1.304,5.876) B14(1.954,5.876) B15(2.604,5.876) B16(3.254,5.876) B17(3.904,5.876) B18(4.554,5.876) B19(5.204,5.876) B20(5.854,5.876) B21(6.504,5.876) C1(-6.496,5.226) C2(-5.846,5.226) C4(-4.546,5.226) C5(-3.896,5.226) C6(-3.246,5.226) C7(-2.596,5.226) C8(-1.946,5.226) C9(-1.296,5.226) C10(-0.646,5.226) C11(0.004,5.226) C12(0.654,5.226) C13(1.304,5.226) C14(1.954,5.226) C15(2.604,5.226) C16(3.254,5.226) C17(3.904,5.226) C18(4.554,5.226) C20(5.854,5.226) C21(6.504,5.226) D1(-6.496,4.576) D2(-5.846,4.576) D3(-5.196,4.576) D4(-4.546,4.576) D6(-3.246,4.576) D7(-2.596,4.576) D9(-1.296,4.576) D10(-0.646,4.576) D12(0.654,4.576) D13(1.304,4.576) D15(2.604,4.576) D16(3.254,4.576) D18(4.554,4.576) D19(5.204,4.576) D20(5.854,4.576) D21(6.504,4.576) E2(-5.846,3.926) E3(-5.196,3.926) E6(-3.246,3.926) E7(-2.596,3.926) E9(-1.296,3.926) E10(-0.646,3.926) E12(0.654,3.926) E13(1.304,3.926) E15(2.604,3.926) E16(3.254,3.926) E19(5.204,3.926) E20(5.854,3.926) F1(-6.496,3.276) F2(-5.846,3.276) F3(-5.196,3.276) F4(-4.546,3.276) F5(-3.896,3.276) F7(-2.596,3.276) F8(-1.946,3.276) F9(-1.296,3.276) F10(-0.646,3.276) F11(0.004,3.276) F12(0.654,3.276) F13(1.304,3.276) F14(1.954,3.276) F15(2.604,3.276) F17(3.904,3.276) F18(4.554,3.276) F19(5.204,3.276) F20(5.854,3.276) F21(6.504,3.276) G1(-6.496,2.626) G2(-5.846,2.626) G3(-5.196,2.626) G4(-4.546,2.626) G5(-3.896,2.626) G6(-3.246,2.626) G16(3.254,2.626) G17(3.904,2.626) G18(4.554,2.626) G19(5.204,2.626) G20(5.854,2.626) G21(6.504,2.626) H2(-5.846,1.976) H3(-5.196,1.976) H6(-3.246,1.976) H8(-1.946,1.976) H9(-1.296,1.976) H10(-0.646,1.976) H11(0.004,1.976) H12(0.654,1.976) H13(1.304,1.976) H14(1.954,1.976) H16(3.254,1.976) H19(5.204,1.976) H20(5.854,1.976) J1(-6.496,1.326) J2(-5.846,1.326) J3(-5.196,1.326) J4(-4.546,1.326) J5(-3.896,1.326) J6(-3.246,1.326) J8(-1.946,1.326) J9(-1.296,1.326) J10(-0.646,1.326) J11(0.004,1.326) J12(0.654,1.326) J13(1.304,1.326) J14(1.954,1.326) J16(3.254,1.326) J17(3.904,1.326) J18(4.554,1.326) J19(5.204,1.326) J20(5.854,1.326) J21(6.504,1.326) K1(-6.496,0.676) K2(-5.846,0.676) K3(-5.196,0.676) K4(-4.546,0.676) K5(-3.896,0.676) K6(-3.246,0.676) K8(-1.946,0.676) K9(-1.296,0.676) K10(-0.646,0.676) K11(0.004,0.676) K12(0.654,0.676) K13(1.304,0.676) K14(1.954,0.676) K16(3.254,0.676) K17(3.904,0.676) K18(4.554,0.676) K19(5.204,0.676) K20(5.854,0.676) K21(6.504,0.676) L2(-5.846,0.026) L3(-5.196,0.026) L6(-3.246,0.026) L8(-1.946,0.026) L9(-1.296,0.026) L10(-0.646,0.026) L11(0.004,0.026) L12(0.654,0.026) L13(1.304,0.026) L14(1.954,0.026) L16(3.254,0.026) L19(5.204,0.026) L20(5.854,0.026) M1(-6.496,-0.624) M2(-5.846,-0.624) M3(-5.196,-0.624) M4(-4.546,-0.624) M5(-3.896,-0.624) M6(-3.246,-0.624) M8(-1.946,-0.624) M9(-1.296,-0.624) M10(-0.646,-0.624) M11(0.004,-0.624) M12(0.654,-0.624) M13(1.304,-0.624) M14(1.954,-0.624) M16(3.254,-0.624) M17(3.904,-0.624) M18(4.554,-0.624) M19(5.204,-0.624) M20(5.854,-0.624) M21(6.504,-0.624) N1(-6.496,-1.274) N2(-5.846,-1.274) N3(-5.196,-1.274) N4(-4.546,-1.274) N5(-3.896,-1.274) N6(-3.246,-1.274) N8(-1.946,-1.274) N9(-1.296,-1.274) N10(-0.646,-1.274) N11(0.004,-1.274) N12(0.654,-1.274) N13(1.304,-1.274) N14(1.954,-1.274) N16(3.254,-1.274) N17(3.904,-1.274) N18(4.554,-1.274) N19(5.204,-1.274) N20(5.854,-1.274) N21(6.504,-1.274) P2(-5.846,-1.924) P3(-5.196,-1.924) P6(-3.246,-1.924) P8(-1.946,-1.924) P9(-1.296,-1.924) P10(-0.646,-1.924) P11(0.004,-1.924) P12(0.654,-1.924) P13(1.304,-1.924) P14(1.954,-1.924) P16(3.254,-1.924) P19(5.204,-1.924) P20(5.854,-1.924) R1(-6.496,-2.574) R2(-5.846,-2.574) R3(-5.196,-2.574) R4(-4.546,-2.574) R5(-3.896,-2.574) R6(-3.246,-2.574) R16(3.254,-2.574) R17(3.904,-2.574) R18(4.554,-2.574) R19(5.204,-2.574) R20(5.854,-2.574) R21(6.504,-2.574) T1(-6.496,-3.224) T2(-5.846,-3.224) T3(-5.196,-3.224) T4(-4.546,-3.224) T5(-3.896,-3.224) T7(-2.596,-3.224) T8(-1.946,-3.224) T9(-1.296,-3.224) T10(-0.646,-3.224) T11(0.004,-3.224) T12(0.654,-3.224) T13(1.304,-3.224) T14(1.954,-3.224) T15(2.604,-3.224) T17(3.904,-3.224) T18(4.554,-3.224) T19(5.204,-3.224) T20(5.854,-3.224) T21(6.504,-3.224) U2(-5.846,-3.874) U3(-5.196,-3.874) U6(-3.246,-3.874) U7(-2.596,-3.874) U9(-1.296,-3.874) U10(-0.646,-3.874) U12(0.654,-3.874) U13(1.304,-3.874) U15(2.604,-3.874) U16(3.254,-3.874) U19(5.204,-3.874) U20(5.854,-3.874) V1(-6.496,-4.524) V2(-5.846,-4.524) V3(-5.196,-4.524) V4(-4.546,-4.524) V6(-3.246,-4.524) V7(-2.596,-4.524) V9(-1.296,-4.524) V10(-0.646,-4.524) V12(0.654,-4.524) V13(1.304,-4.524) V15(2.604,-4.524) V16(3.254,-4.524) V18(4.554,-4.524) V19(5.204,-4.524) V20(5.854,-4.524) V21(6.504,-4.524) W1(-6.496,-5.174) W2(-5.846,-5.174) W4(-4.546,-5.174) W5(-3.896,-5.174) W6(-3.246,-5.174) W7(-2.596,-5.174) W8(-1.946,-5.174) W9(-1.296,-5.174) W10(-0.646,-5.174) W11(0.004,-5.174) W12(0.654,-5.174) W13(1.304,-5.174) W14(1.954,-5.174) W15(2.604,-5.174) W16(3.254,-5.174) W17(3.904,-5.174) W18(4.554,-5.174) W20(5.854,-5.174) W21(6.504,-5.174) Y1(-6.496,-5.824) Y2(-5.846,-5.824) Y3(-5.196,-5.824) Y4(-4.546,-5.824) Y5(-3.896,-5.824) Y6(-3.246,-5.824) Y7(-2.596,-5.824) Y8(-1.946,-5.824) Y9(-1.296,-5.824) Y10(-0.646,-5.824) Y11(0.004,-5.824) Y12(0.654,-5.824) Y13(1.304,-5.824) Y14(1.954,-5.824) Y15(2.604,-5.824) Y16(3.254,-5.824) Y17(3.904,-5.824) Y18(4.554,-5.824) Y19(5.204,-5.824) Y20(5.854,-5.824) Y21(6.504,-5.824)
  silkscreen extent -7.42,-6.97 7,7.79
BMI160 [mm] "QFN, 14-Leads, Body 2.6x3.1mm (max), Pitch 0.50mm, IPC Medium Density"
  rect 0.75x0.3 smd: 1(-1.525,0.75) 2(-1.525,0.25) 3(-1.525,-0.25) 4(-1.525,-0.75) 8(1.525,-0.75) 9(1.525,-0.25) 10(1.525,0.25) 11(1.525,0.75)
  rect 0.3x0.75 smd: 5(-0.5,-1.275) 6(0,-1.275) 7(0.5,-1.275) 12(0.5,1.275) 13(0,1.275) 14(-0.5,1.275)
  silkscreen extent -2.57,-1.3 1.55,1.3
C0402 [mm] "C0402"
  rect 0.51x0.51 smd: 1(-0.41,0) 2(0.41,0)
  silkscreen extent -0.91,-0.5 0.91,0.5
C0603 [mil] "C0603"
  rect 31.5x35.43 smd: 1(-28.06,0) 2(27.06,0)
  silkscreen extent -50,-24 50,24
C0805 [mil] "C0805"
  oval 40x50 smd: 1(-35,0) 2(35,0)
  silkscreen extent -60,-30 60,30
CD32 [mm]
  rect 4.2x1.6 smd: 1(0,-1.3) 2(0,1.3)
  silkscreen extent -2.25,-2.25 2.25,2.25, body extent -2.09,-1.7 2.1,1.79, height 2.2
CD43 [mm]
  rect 4.2x1.6 smd: 1(0,-1.3) 2(0,1.3)
  silkscreen extent -2.25,-2.25 2.25,2.25, body extent -2.09,-1.7 2.1,1.79, height 2.2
